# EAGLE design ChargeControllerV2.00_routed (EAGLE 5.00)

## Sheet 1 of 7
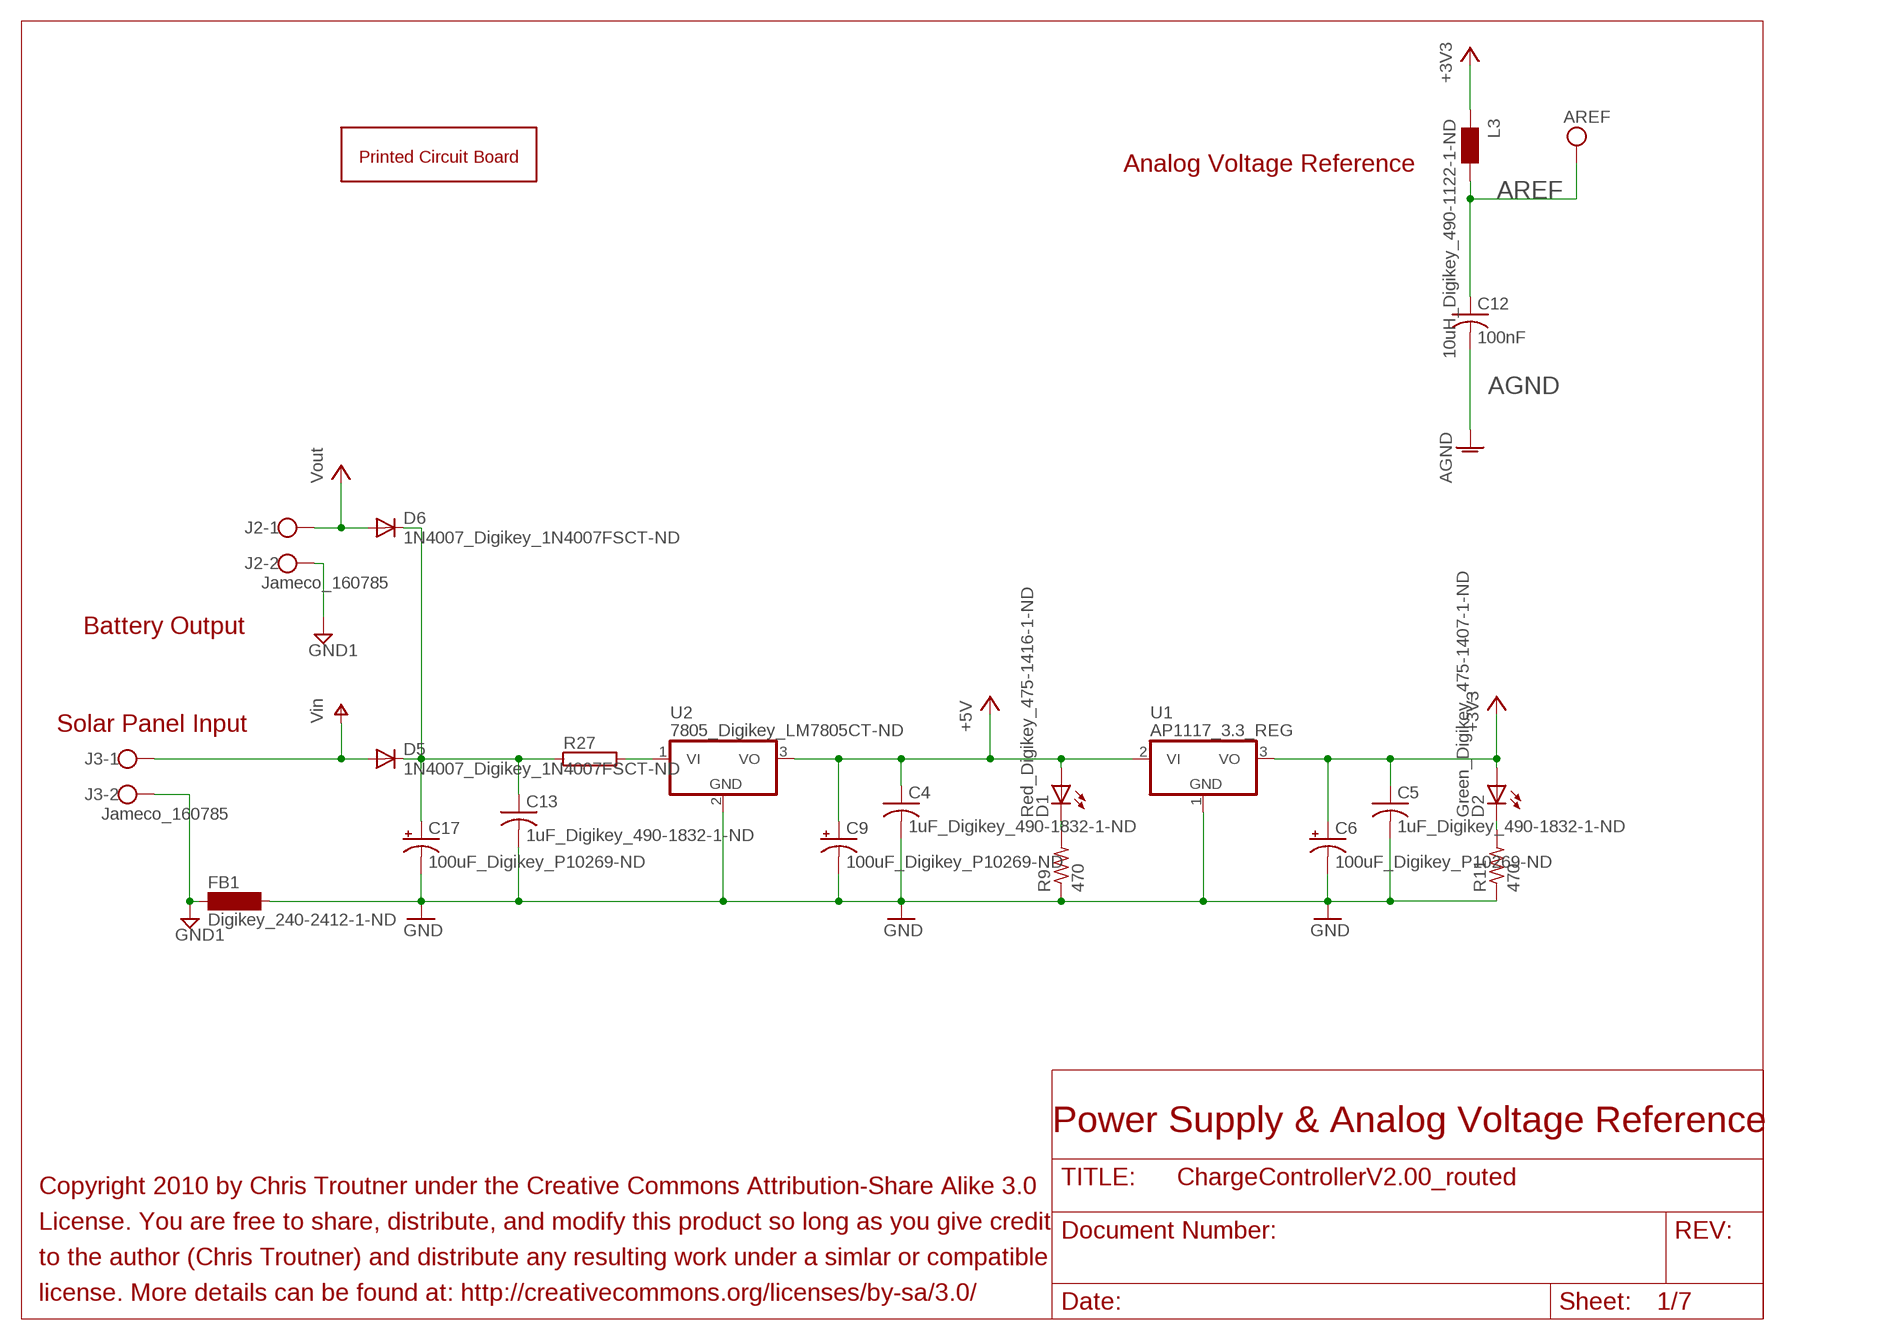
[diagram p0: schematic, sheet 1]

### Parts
C4  1uF_Digikey_490-1832-1-ND  C-USC1206K  [C1206K]
C5  1uF_Digikey_490-1832-1-ND  C-USC1206K  [C1206K]
C6  100uF_Digikey_P10269-ND  CPOL-USE2.5-7  [E2,5-7]
C9  100uF_Digikey_P10269-ND  CPOL-USE2.5-7  [E2,5-7]
C12  100nF  C-USC1206K  [C1206K]
C13  1uF_Digikey_490-1832-1-ND  C-USC1206K  [C1206K]
C17  100uF_Digikey_P10269-ND  CPOL-USE2.5-7  [E2,5-7]
D1  Red_Digikey_475-1416-1-ND  LEDCHIPLED_1206  [CHIPLED_1206]
D2  Green_Digikey_475-1407-1-ND  LEDCHIPLED_1206  [CHIPLED_1206]
D5  1N4007_Digikey_1N4007FSCT-ND  1N4004  [DO41-10]
D6  1N4007_Digikey_1N4007FSCT-ND  1N4004  [DO41-10]
FB1  Digikey_240-2412-1-ND  SM-1206  [SM-1206]
J2  Jameco_160785  W237-102  [W237-102]
J3  Jameco_160785  W237-102  [W237-102]
L3  10uH_Digikey_490-1122-1-ND  WE-MK_0805  [0805]
R9  470  R-US_R1206  [R1206]
R11  470  R-US_R1206  [R1206]
R27  RMPC70-2  [MPC70-2]
U1  AP1117_3.3_REG  [TO252]
U2  7805_Digikey_LM7805CT-ND  7805T  [TO220H]
U$1  PCB_RM2015S  [PCB_RM2015S]

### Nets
+3V3: C5.1 C6.+ D2.A L3.1 U1.3(VO) ; also sheet 6
+5V: C4.1 C9.+ D1.A U1.2(VI) U2.3(VO) ; also sheet 2,3,4,5,6
AGND: C12.2 ; also sheet 5
AREF: C12.1 L3.2
GND: C4.2 C5.2 C6.- C9.- C13.2 C17.- FB1.2 R9.1 R11.1 U1.1(GND) U2.2(GND) ; also sheet 2,3,4,5,6
GND1: FB1.1 J2.2 J3.2 ; also sheet 2
N$1: C13.1 C17.+ D5.C D6.C R27.1
N$3: R27.2 U2.1(VI)
N$5: D1.C R9.2
N$6: D2.C R11.2
N$35: D6.A J2.1 ; supply symbol labelled Vout ; also sheet 2,3
VIN: D5.A J3.1 ; supply symbol labelled Vin ; also sheet 2,3

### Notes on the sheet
- Analog Voltage Reference
- Battery Output
- Solar Panel Input
- Power Supply & Analog Voltage Reference
- Copyright 2010 by Chris Troutner under the Creative Commons Attribution-Share Alike 3.0
- License. You are free to share, distribute, and modify this product so long as you give credit
- to the author (Chris Troutner) and distribute any resulting work under a simlar or compatible
- license. More details can be found at: http://creativecommons.org/licenses/by-sa/3.0/

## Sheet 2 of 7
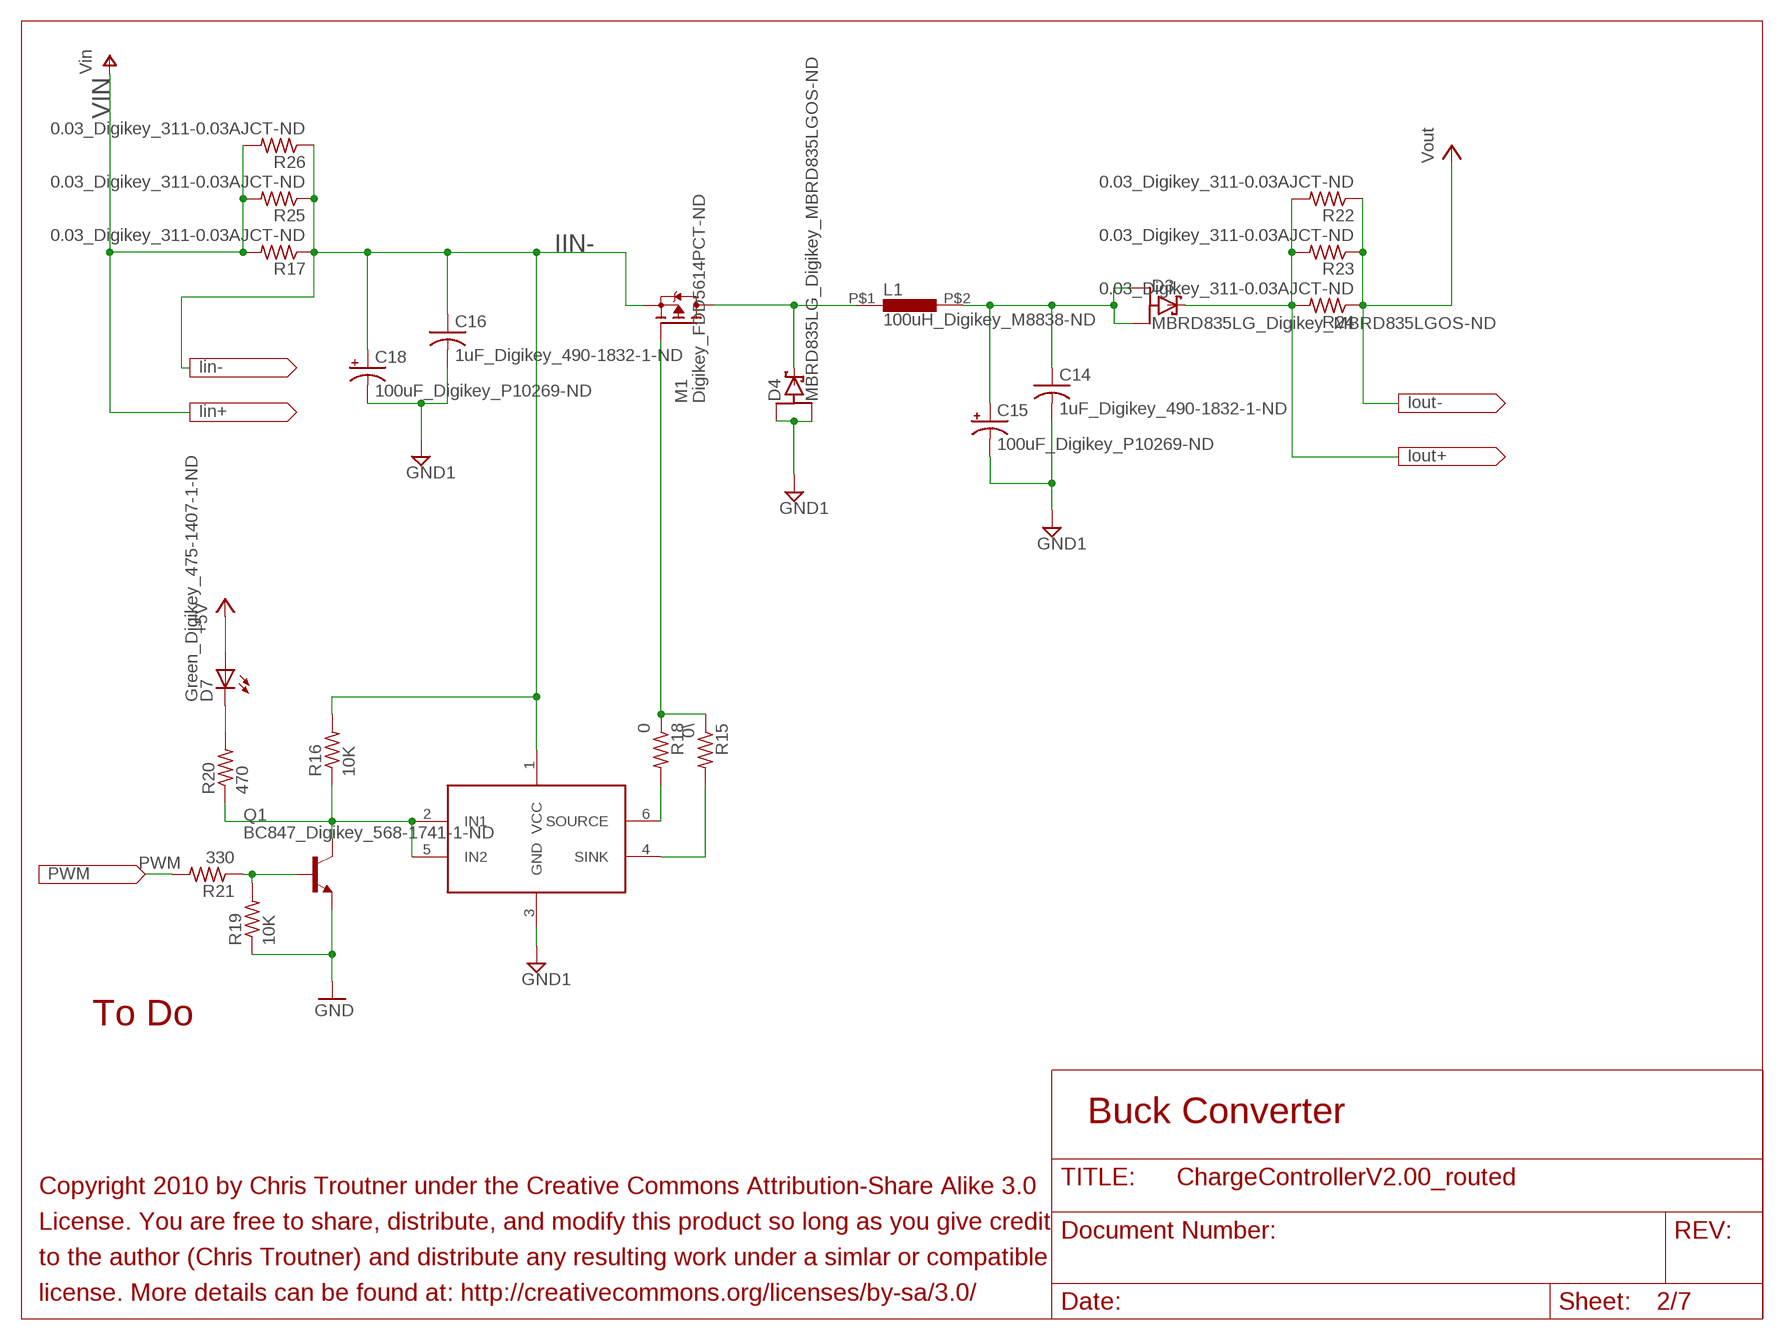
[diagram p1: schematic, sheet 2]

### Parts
C14  1uF_Digikey_490-1832-1-ND  C-USC1206K  [C1206K]
C15  100uF_Digikey_P10269-ND  CPOL-USE2.5-7  [E2,5-7]
C16  1uF_Digikey_490-1832-1-ND  C-USC1206K  [C1206K]
C18  100uF_Digikey_P10269-ND  CPOL-USE2.5-7  [E2,5-7]
D3  MBRD835LG_Digikey_MBRD835LGOS-ND  DIODE_SCHOTTKY_MBRD835LG  [DPAK_TO252]
D4  MBRD835LG_Digikey_MBRD835LGOS-ND  DIODE_SCHOTTKY_MBRD835LG  [DPAK_TO252]
D7  Green_Digikey_475-1407-1-ND  LEDCHIPLED_1206  [CHIPLED_1206]
L1  100uH_Digikey_M8838-ND  2312-RC  [2312-RC]
M1  Digikey_FDD5614PCT-ND  SPD30P06PTO252  [TO252]
Q1  BC847_Digikey_568-1741-1-ND  BC849SMD  [SOT23-BEC]
R15  0\  R-US_R1206  [R1206]
R16  10K  R-US_R1206  [R1206]
R17  0.03_Digikey_311-0.03AJCT-ND  R-US_R1206  [R1206]
R18  0  R-US_R1206  [R1206]
R19  10K  R-US_R1206  [R1206]
R20  470  R-US_R1206  [R1206]
R21  330  R-US_R1206  [R1206]
R22  0.03_Digikey_311-0.03AJCT-ND  R-US_R1206  [R1206]
R23  0.03_Digikey_311-0.03AJCT-ND  R-US_R1206  [R1206]
R24  0.03_Digikey_311-0.03AJCT-ND  R-US_R1206  [R1206]
R25  0.03_Digikey_311-0.03AJCT-ND  R-US_R1206  [R1206]
R26  0.03_Digikey_311-0.03AJCT-ND  R-US_R1206  [R1206]
U4  Digikey_ZXGD3003E6CT-ND  ZXGD3003  [SOT23-6]

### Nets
+5V: D7.A ; also sheet 1,3,4,5,6
GND: Q1.E R19.1 ; also sheet 1,3,4,5,6
GND1: C14.2 C15.- C16.2 C18.- D4.1(A) D4.3(A1) U4.3(GND) ; also sheet 1
IIN-: C16.1 C18.+ M1.2(S) R16.2 R17.1 R25.1 R26.1 U4.1(VCC) ; also sheet 3
IOUT+: D3.4(C) R22.2 R23.2 R24.2 ; also sheet 3
N$8: R18.2 U4.6(SOURCE)
N$9: D7.C R20.2
N$10: Q1.B R19.2 R21.1
N$16: R15.2 U4.4(SINK)
N$21: M1.1(G) R15.1 R18.1
N$24: Q1.C R16.1 R20.1 U4.2(IN1) U4.5(IN2)
N$30: D4.4(C) L1.P$1 M1.3(D)
N$34: C14.1 C15.+ D3.1(A) D3.3(A1) L1.P$2
N$35: R22.1 R23.1 R24.1 ; supply symbol labelled Vout ; also sheet 1,3
PWM: R21.2 ; also sheet 5
VIN: R17.2 R25.2 R26.2 ; supply symbol labelled Vin ; also sheet 1,3

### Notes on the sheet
- To Do
- Buck Converter
- Copyright 2010 by Chris Troutner under the Creative Commons Attribution-Share Alike 3.0
- License. You are free to share, distribute, and modify this product so long as you give credit
- to the author (Chris Troutner) and distribute any resulting work under a simlar or compatible
- license. More details can be found at: http://creativecommons.org/licenses/by-sa/3.0/

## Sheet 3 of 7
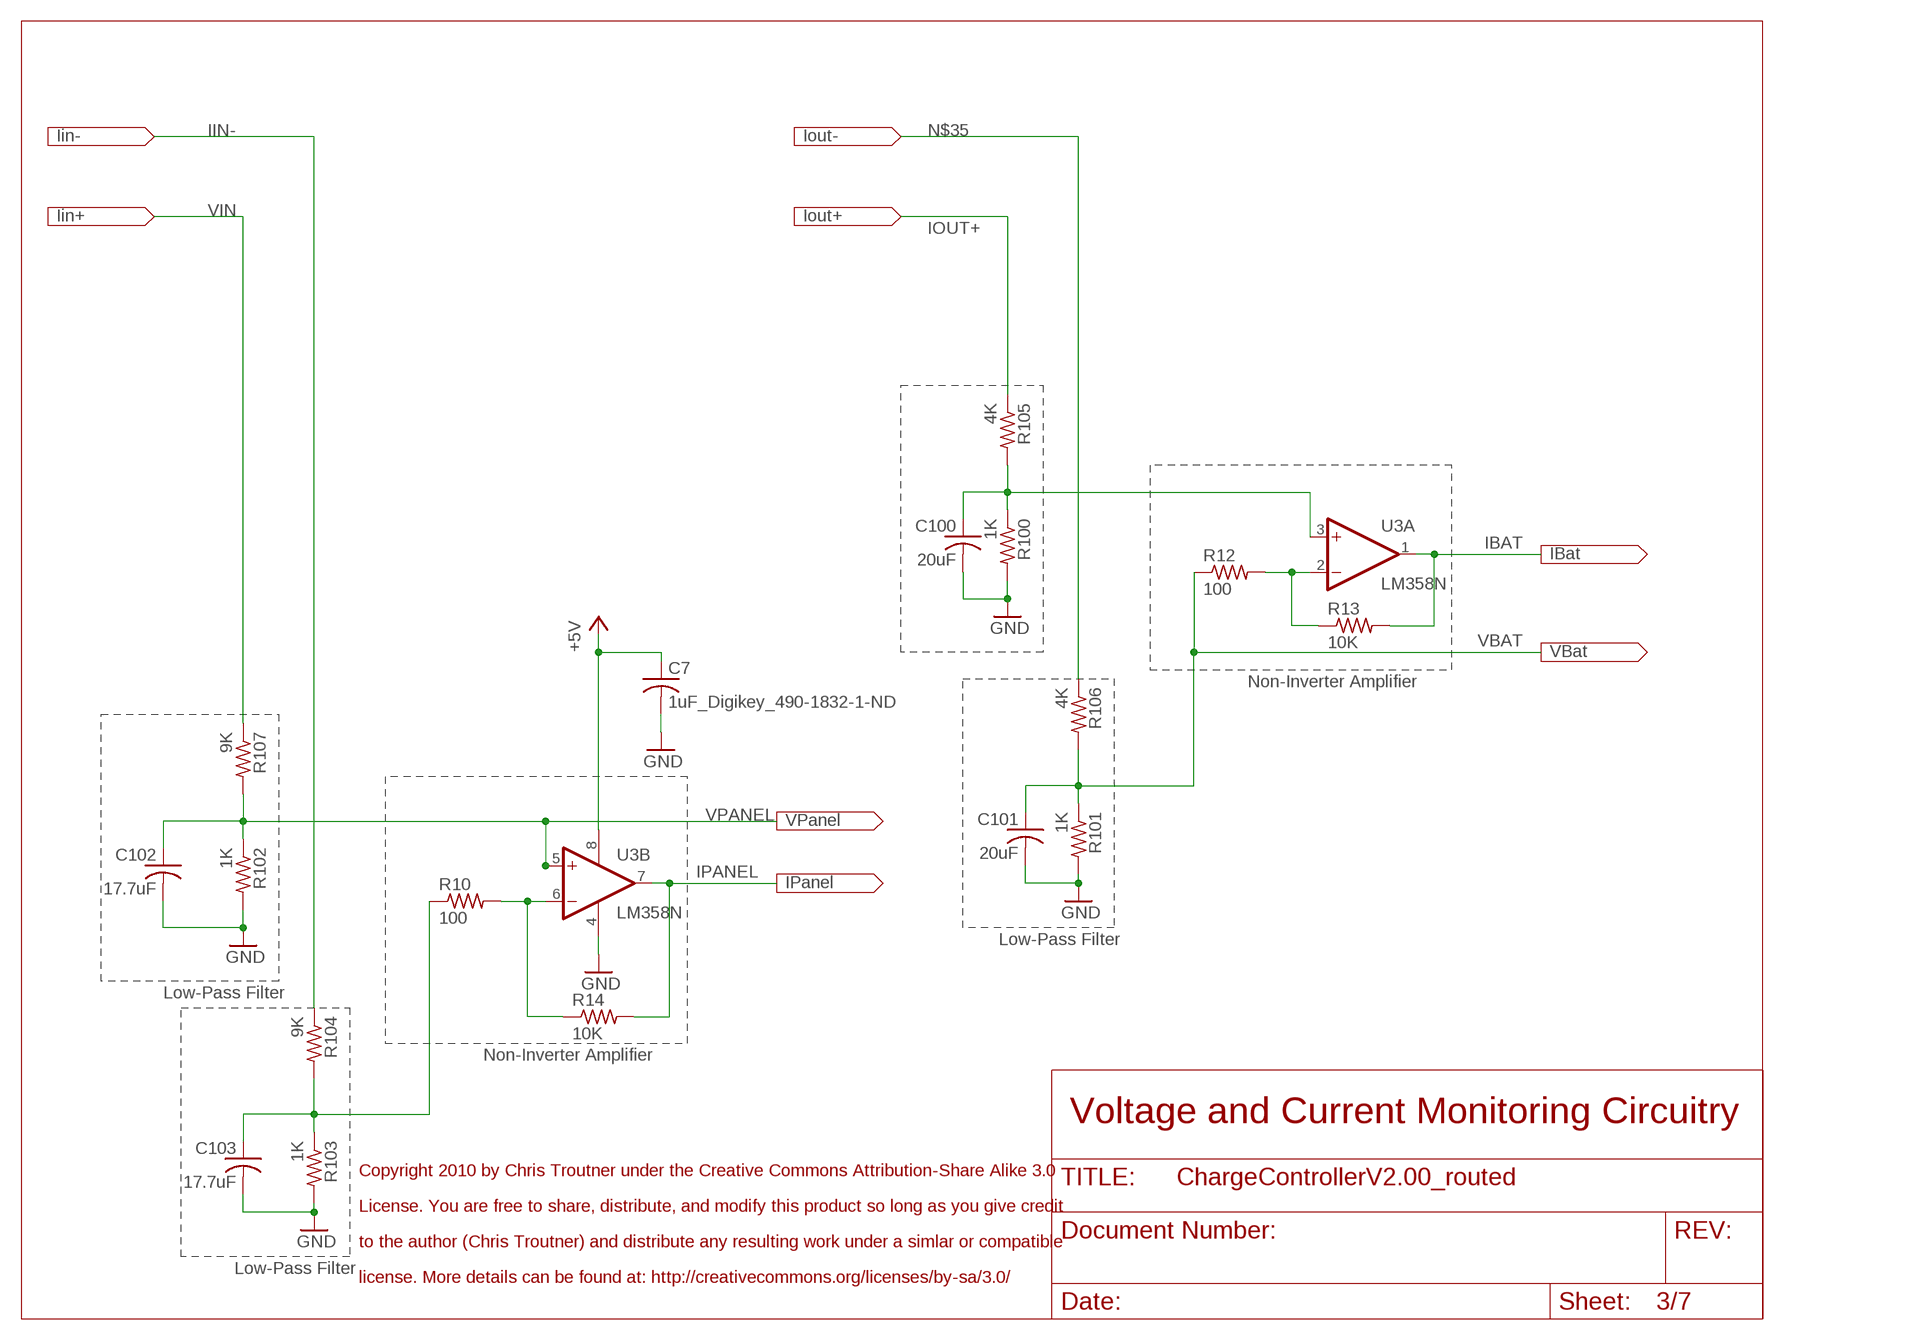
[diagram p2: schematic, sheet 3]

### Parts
C7  1uF_Digikey_490-1832-1-ND  C-USC1206K  [C1206K]
C100  20uF  C-USC1206K  [C1206K]
C101  20uF  C-USC1206K  [C1206K]
C102  17.7uF  C-USC1206K  [C1206K]
C103  17.7uF  C-USC1206K  [C1206K]
R10  100  R-US_R1206  [R1206]
R12  100  R-US_R1206  [R1206]
R13  10K  R-US_R1206  [R1206]
R14  10K  R-US_R1206  [R1206]
R100  1K  R-US_R1206  [R1206]
R101  1K  R-US_R1206  [R1206]
R102  1K  R-US_R1206  [R1206]
R103  1K  R-US_R1206  [R1206]
R104  9K  R-US_R1206  [R1206]
R105  4K  R-US_R1206  [R1206]
R106  4K  R-US_R1206  [R1206]
R107  9K  R-US_R1206  [R1206]
U3  LM358N  [DIL08]

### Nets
+5V: C7.1 U3.8(P:V+) ; also sheet 1,2,4,5,6
BLAH1: C103.1 R10.1 R103.1 R104.2
GND: C7.2 C100.2 C101.2 C102.2 C103.2 R100.2 R101.2 R102.2 R103.2 U3.4(P:V-) ; also sheet 1,2,4,5,6
IBAT: R13.2 U3.1(A:OUT) ; also sheet 5
IIN-: R104.1 ; also sheet 2
IOUT+: R105.1 ; also sheet 2
IPANEL: R14.2 U3.7(B:OUT) ; also sheet 5
N$12: R12.2 R13.1 U3.2(A:-IN)
N$14: R10.2 R14.1 U3.6(B:-IN)
N$35: R106.1 ; also sheet 1,2
VBAT: C101.1 R12.1 R101.1 R106.2 ; also sheet 5
VIN: R107.1 ; also sheet 1,2
VOP+: C100.1 R100.1 R105.2 U3.3(A:+IN)
VPANEL: C102.1 R102.1 R107.2 U3.5(B:+IN) ; also sheet 5

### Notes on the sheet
- Non-Inverter Amplifier
- Low-Pass Filter
- Low-Pass Filter
- Non-Inverter Amplifier
- Voltage and Current Monitoring Circuitry
- Copyright 2010 by Chris Troutner under the Creative Commons Attribution-Share Alike 3.0
- License. You are free to share, distribute, and modify this product so long as you give credit
- to the author (Chris Troutner) and distribute any resulting work under a simlar or compatible
- Low-Pass Filter
- license. More details can be found at: http://creativecommons.org/licenses/by-sa/3.0/

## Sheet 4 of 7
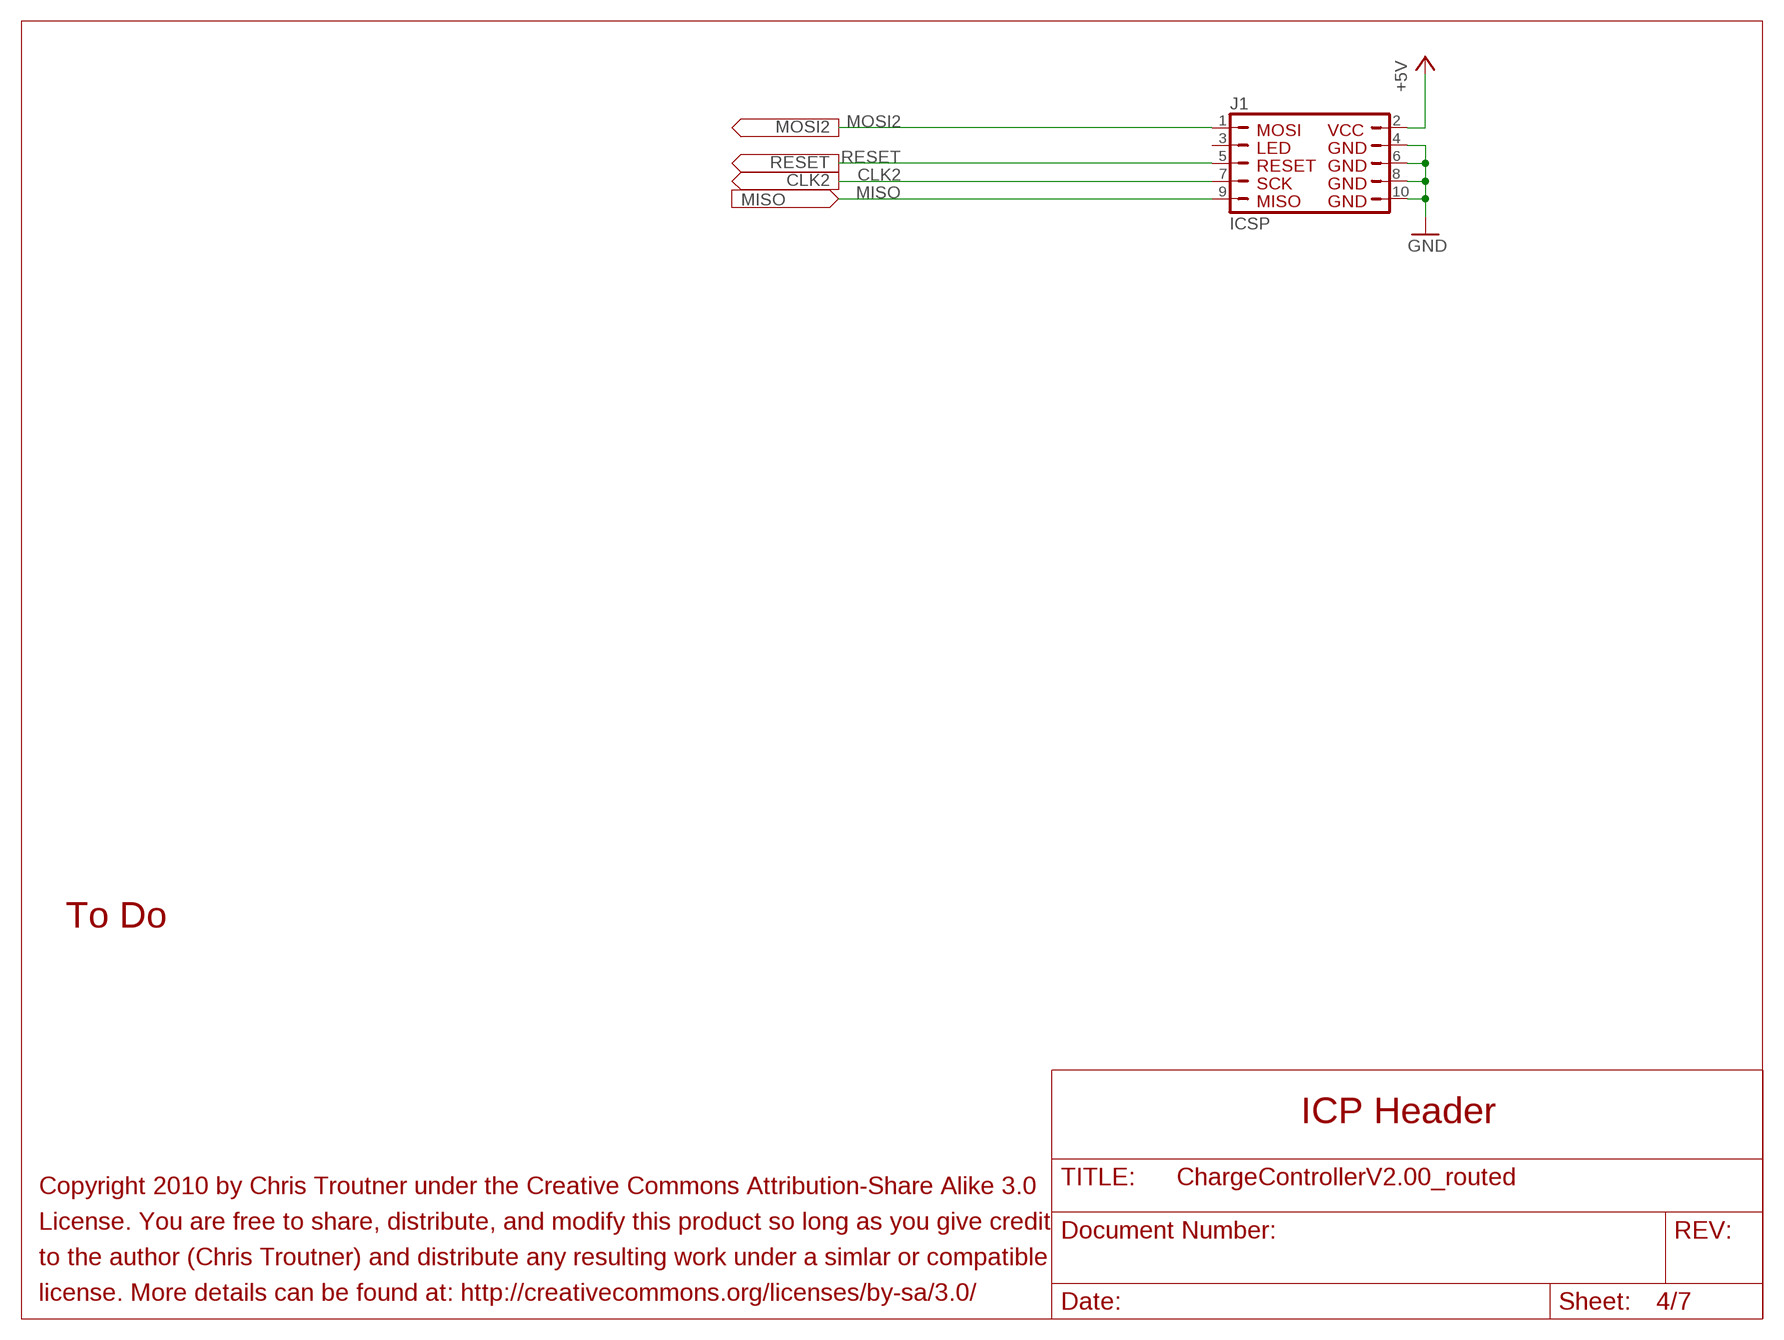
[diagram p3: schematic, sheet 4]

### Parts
J1  ICSP  [ICSP]

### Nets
+5V: J1.2 ; also sheet 1,2,3,5,6
CLK2: J1.7 ; also sheet 5,6
GND: J1.4 J1.6 J1.8 J1.10 ; also sheet 1,2,3,5,6
MISO: J1.9 ; also sheet 5,6
MOSI2: J1.1 ; also sheet 5,6
RESET: J1.5 ; also sheet 5
Unconnected: J1.3

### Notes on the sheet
- To Do
- ICP Header
- Copyright 2010 by Chris Troutner under the Creative Commons Attribution-Share Alike 3.0
- License. You are free to share, distribute, and modify this product so long as you give credit
- to the author (Chris Troutner) and distribute any resulting work under a simlar or compatible
- license. More details can be found at: http://creativecommons.org/licenses/by-sa/3.0/

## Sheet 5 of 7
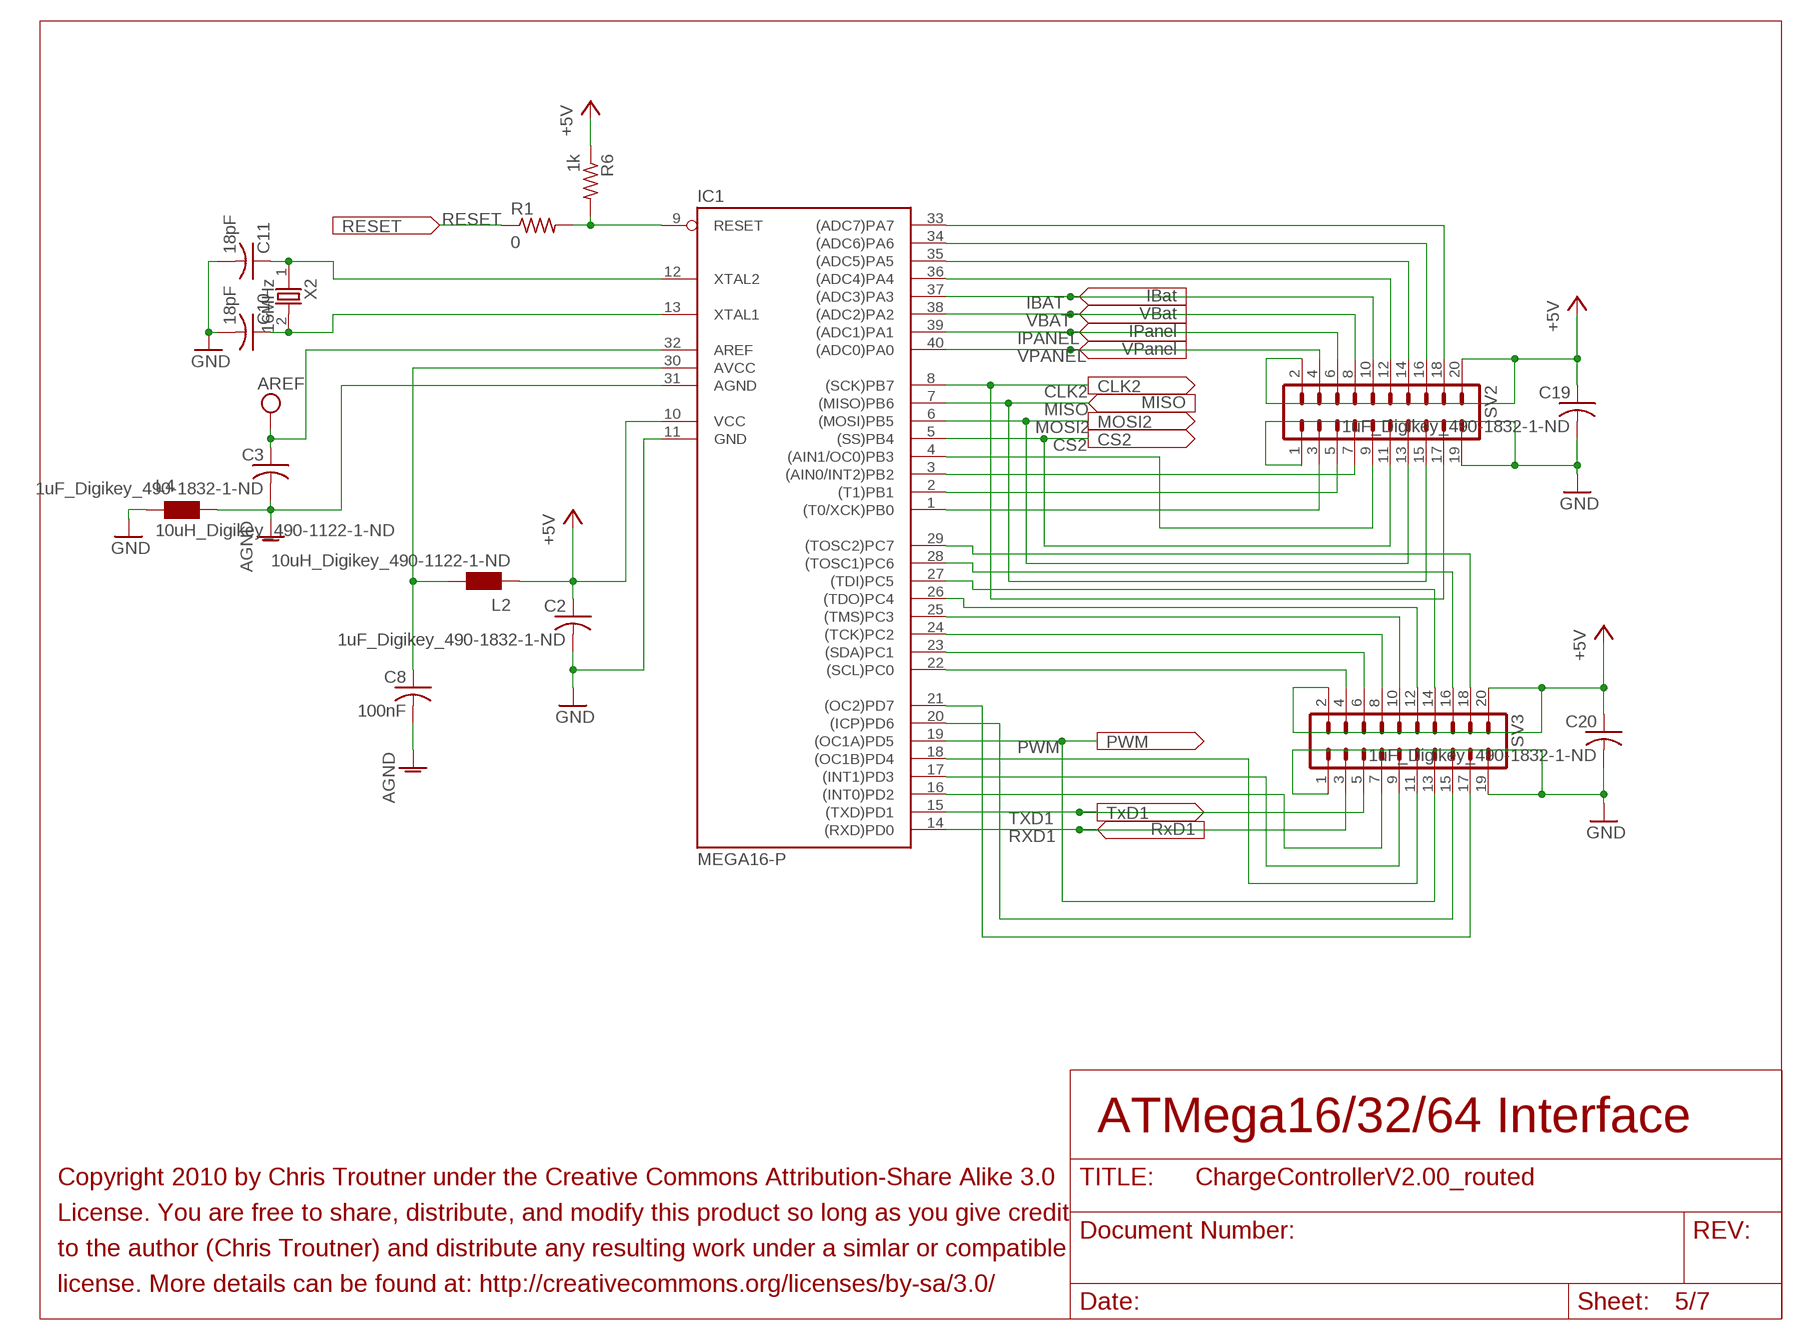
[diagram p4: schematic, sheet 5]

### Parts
C2  1uF_Digikey_490-1832-1-ND  C-USC1206K  [C1206K]
C3  1uF_Digikey_490-1832-1-ND  C-USC1206K  [C1206K]
C8  100nF  C-USC1206K  [C1206K]
C10  18pF  C-USC1206K  [C1206K]
C11  18pF  C-USC1206K  [C1206K]
C19  1uF_Digikey_490-1832-1-ND  C-USC1206K  [C1206K]
C20  1uF_Digikey_490-1832-1-ND  C-USC1206K  [C1206K]
IC1  MEGA16-P  [DIL40]
L2  10uH_Digikey_490-1122-1-ND  WE-MK_0805  [0805]
L4  10uH_Digikey_490-1122-1-ND  WE-MK_0805  [0805]
R1  0  R-US_R1206  [R1206]
R6  1k  R-US_R1206  [R1206]
SV2  MA10-2  [MA10-2]
SV3  MA10-2  [MA10-2]
X2  16MHz  20MHZ_XTL  [HS49S]

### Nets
+5V: C2.1 C19.1 C20.1 IC1.10(VCC) L2.1 R6.1 SV2.2 SV2.20 SV3.2 SV3.20 ; also sheet 1,2,3,4,6
AGND: C3.2 C8.2 IC1.31(AGND) L4.2 ; also sheet 1
CLK2: IC1.8((SCK)PB7) SV2.17 ; also sheet 4,6
CS2: IC1.5((SS)PB4) SV2.11 ; also sheet 6
GND: C2.2 C10.2 C11.2 C19.2 C20.2 IC1.11(GND) L4.1 SV2.1 SV2.19 SV3.1 SV3.19 ; also sheet 1,2,3,4,6
IBAT: IC1.37((ADC3)PA3) SV2.10 ; also sheet 3
IPANEL: IC1.39((ADC1)PA1) SV2.6 ; also sheet 3
MISO: IC1.7((MISO)PB6) SV2.15 ; also sheet 4,6
MOSI2: IC1.6((MOSI)PB5) SV2.13 ; also sheet 4,6
N$7: C8.1 IC1.30(AVCC) L2.2
N$15: C11.1 IC1.12(XTAL2) X2.1
N$17: C10.1 IC1.13(XTAL1) X2.2
N$18: IC1.9(RESET) R1.2 R6.2
N$19: IC1.33((ADC7)PA7) SV2.18
N$20: IC1.34((ADC6)PA6) SV2.16
N$22: IC1.35((ADC5)PA5) SV2.14
N$23: IC1.36((ADC4)PA4) SV2.12
N$27: IC1.1((T0/XCK)PB0) SV2.3
N$62: IC1.2((T1)PB1) SV2.5
N$67: IC1.3((AIN0/INT2)PB2) SV2.7
N$68: IC1.4((AIN1/OC0)PB3) SV2.9
N$69: IC1.16((INT0)PD2) SV3.7
N$70: IC1.17((INT1)PD3) SV3.9
N$71: IC1.22((SCL)PC0) SV3.4
N$72: IC1.23((SDA)PC1) SV3.6
N$73: IC1.24((TCK)PC2) SV3.8
N$74: IC1.25((TMS)PC3) SV3.10
N$75: IC1.26((TDO)PC4) SV3.12
N$76: IC1.27((TDI)PC5) SV3.14
N$77: IC1.28((TOSC1)PC6) SV3.16
N$78: IC1.29((TOSC2)PC7) SV3.18
N$79: IC1.18((OC1B)PD4) SV3.11
N$80: IC1.20((ICP)PD6) SV3.15
N$81: IC1.21((OC2)PD7) SV3.17
PWM: IC1.19((OC1A)PD5) SV3.13 ; also sheet 2
RESET: R1.1 ; also sheet 4
RXD1: IC1.14((RXD)PD0) SV3.3 ; also sheet 6
TXD1: IC1.15((TXD)PD1) SV3.5 ; also sheet 6
VBAT: IC1.38((ADC2)PA2) SV2.8 ; also sheet 3
VDD: C3.1 IC1.32(AREF) ; supply symbol labelled AREF
VPANEL: IC1.40((ADC0)PA0) SV2.4 ; also sheet 3

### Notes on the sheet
- ATMega16/32/64 Interface
- Copyright 2010 by Chris Troutner under the Creative Commons Attribution-Share Alike 3.0
- License. You are free to share, distribute, and modify this product so long as you give credit
- to the author (Chris Troutner) and distribute any resulting work under a simlar or compatible
- license. More details can be found at: http://creativecommons.org/licenses/by-sa/3.0/

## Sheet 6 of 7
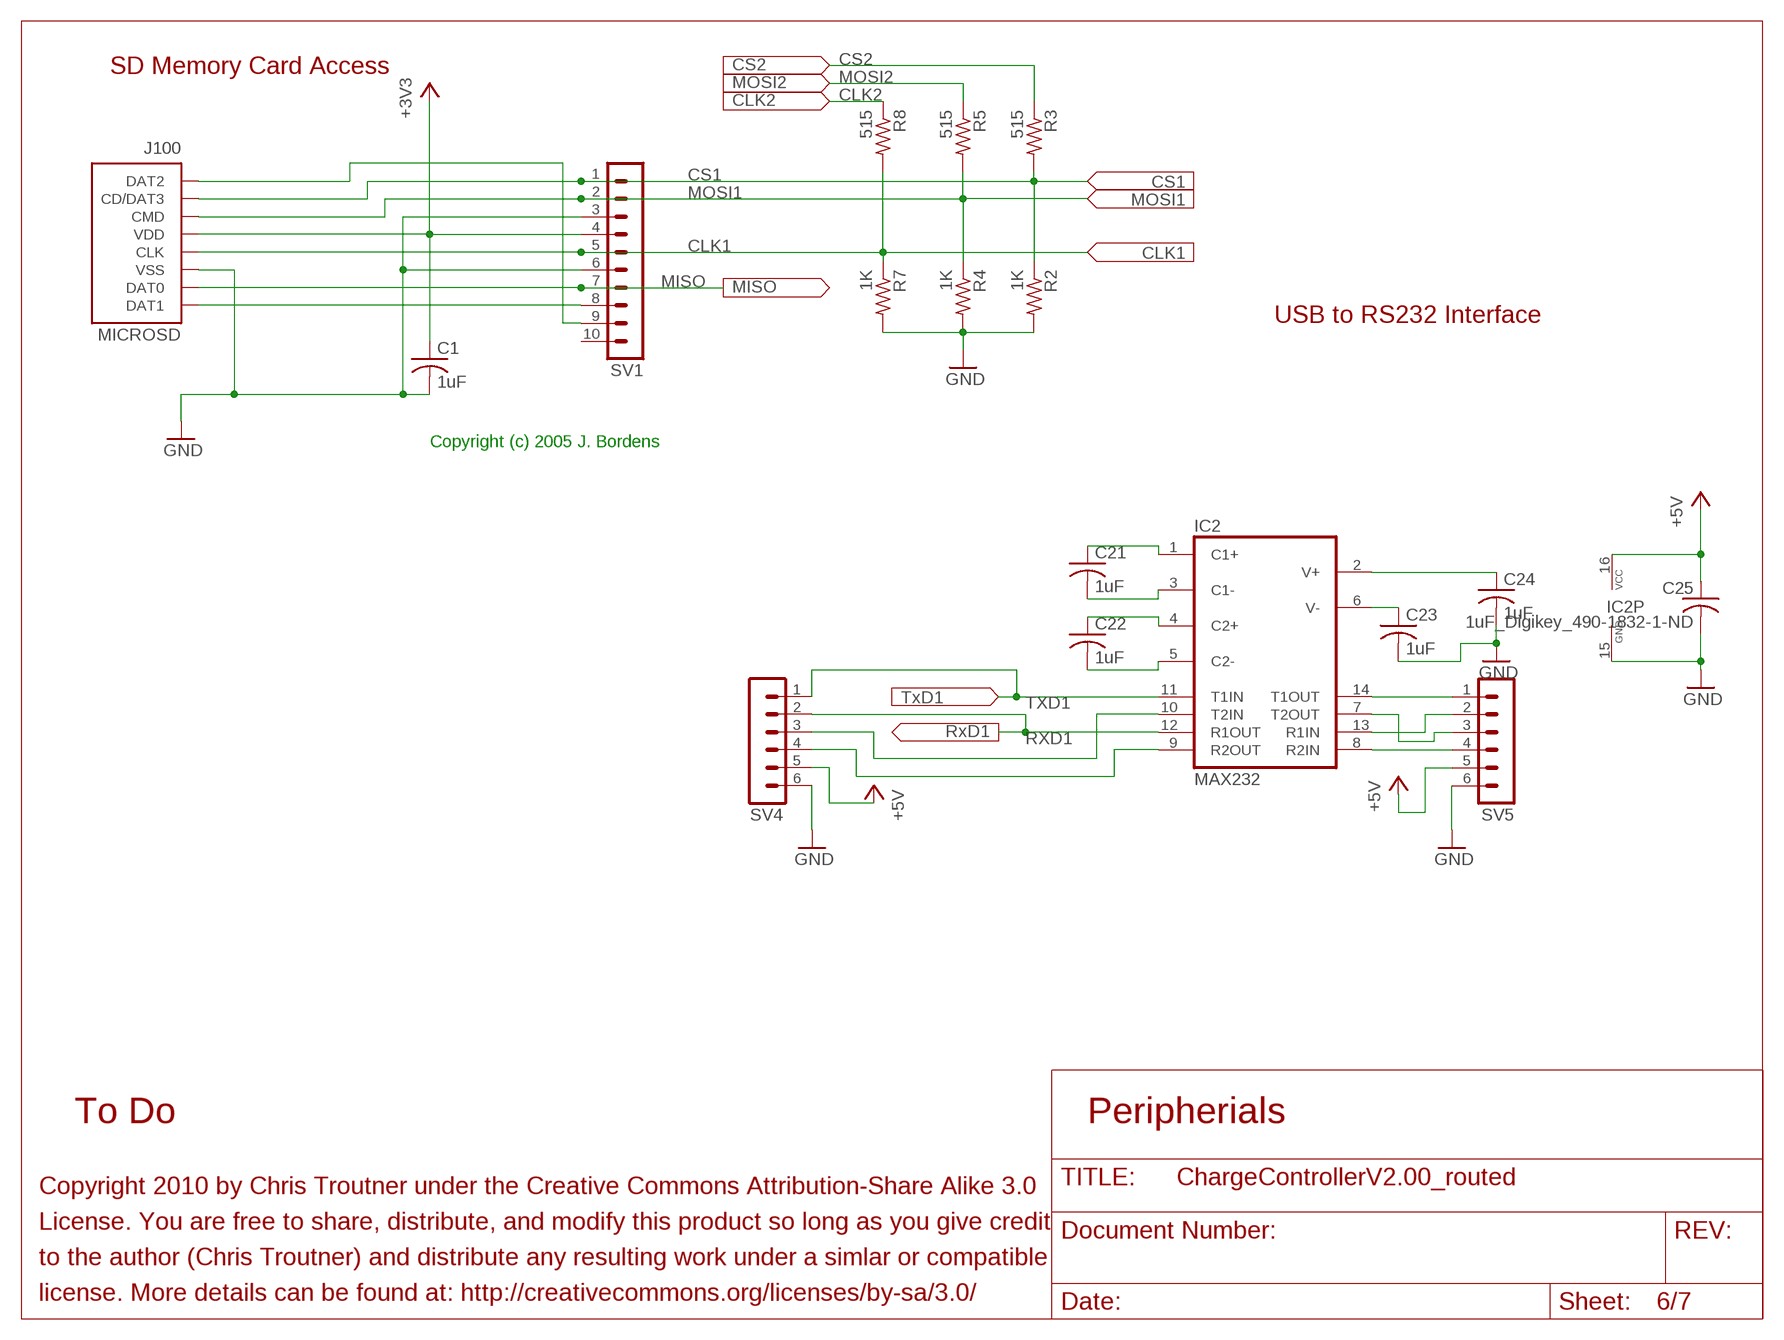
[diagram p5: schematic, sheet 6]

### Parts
C1  1uF  C-USC1206K  [C1206K]
C21  1uF  C-USC1206K  [C1206K]
C22  1uF  C-USC1206K  [C1206K]
C23  1uF  C-USC1206K  [C1206K]
C24  1uF  C-USC1206K  [C1206K]
C25  1uF_Digikey_490-1832-1-ND  C-USC1206K  [C1206K]
IC2  MAX232  [DIL16]
J100  MICROSD  [DM3D_SD_MEMORY]
R2  1K  R-US_R1206  [R1206]
R3  515  R-US_R1206  [R1206]
R4  1K  R-US_R1206  [R1206]
R5  515  R-US_R1206  [R1206]
R7  1K  R-US_R1206  [R1206]
R8  515  R-US_R1206  [R1206]
SV1  MA10-1  [MA10-1]
SV4  MA06-1  [MA06-1]
SV5  MA06-1  [MA06-1]

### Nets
+3V3: C1.1 J100.P$5(VDD) SV1.4 ; also sheet 1
+5V: C25.1 IC2.16(VCC) SV4.5 SV5.5 ; also sheet 1,2,3,4,5
CLK1: J100.P$4(CLK) R7.1 R8.2 SV1.5
CLK2: R8.1 ; also sheet 4,5
CS1: J100.P$7(CD/DAT3) R2.1 R3.2 SV1.1
CS2: R3.1 ; also sheet 5
GND: C1.2 C23.2 C24.2 C25.2 IC2.15(GND) J100.P$3(VSS) R2.2 R4.2 R7.2 SV1.3 SV1.6 SV4.6 SV5.6 ; also sheet 1,2,3,4,5
MISO: J100.P$2(DAT0) SV1.7 ; also sheet 4,5
MOSI1: J100.P$6(CMD) R4.1 R5.2 SV1.2
MOSI2: R5.1 ; also sheet 4,5
N$2: C22.1 IC2.4(C2+)
N$4: C22.2 IC2.5(C2-)
N$11: C21.2 IC2.3(C1-)
N$13: C21.1 IC2.1(C1+)
N$26: J100.P$8(DAT2) SV1.9
N$28: C23.1 IC2.6(V-)
N$29: J100.P$1(DAT1) SV1.8
N$31: C24.1 IC2.2(V+)
N$32: IC2.10(T2IN) SV4.3
N$33: IC2.9(R2OUT) SV4.4
N$36: IC2.14(T1OUT) SV5.1
N$37: IC2.13(R1IN) SV5.2
N$38: IC2.7(T2OUT) SV5.3
N$39: IC2.8(R2IN) SV5.4
RXD1: IC2.12(R1OUT) SV4.2 ; also sheet 5
TXD1: IC2.11(T1IN) SV4.1 ; also sheet 5
Unconnected: SV1.10

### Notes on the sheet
- SD Memory Card Access
- USB to RS232 Interface
- Copyright (c) 2005 J. Bordens
- To Do | Peripherials
- Copyright 2010 by Chris Troutner under the Creative Commons Attribution-Share Alike 3.0
- License. You are free to share, distribute, and modify this product so long as you give credit
- to the author (Chris Troutner) and distribute any resulting work under a simlar or compatible
- license. More details can be found at: http://creativecommons.org/licenses/by-sa/3.0/

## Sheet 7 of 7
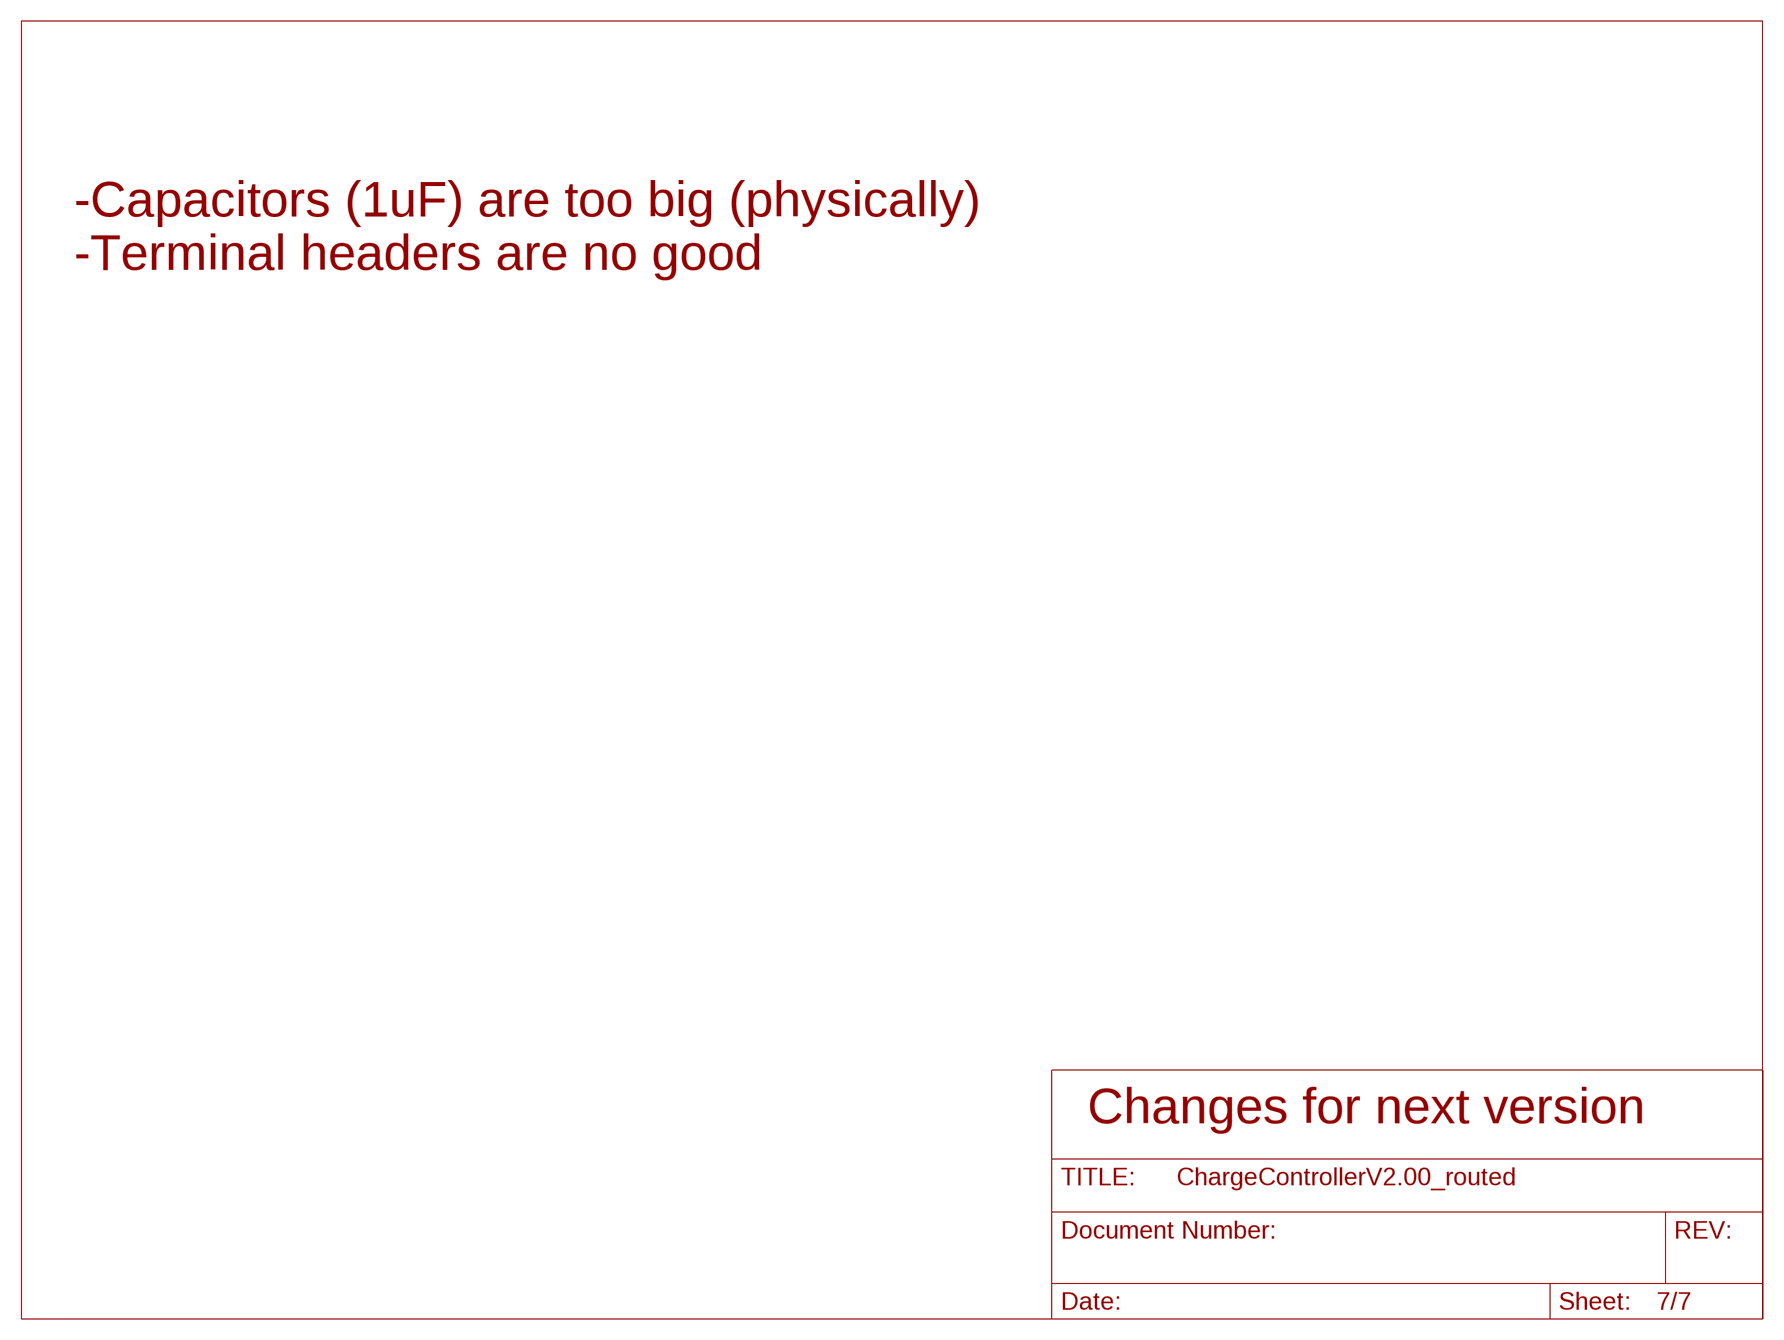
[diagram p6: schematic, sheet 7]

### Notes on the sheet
- -Capacitors (1uF) are too big (physically)
- -Terminal headers are no good
- Changes for next version

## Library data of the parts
C1-C5 C7 C8 C10-C14 C16 C19-C25 C100-C103 = rcl:C-US: CAPACITOR, American symbol
C6 C9 C15 C17 C18 = rcl:CPOL-US: POLARIZED CAPACITOR, American symbol
D1 D2 D7 = led:LED: LED
D3 D4 = EV:DIODE_SCHOTTKY_MBRD835LG: Schottkey diode from ON Semiconductor part # MBRD835LG. Digikey # MBRD835LGOS-ND
D5 D6 = diode:1N4004: DIODE
FB1 = inductor-neosid:SM-1206: INDUCTOR
IC1 = atmel:MEGA16-P: MICROCONTROLLER 16 Kbytes FLASH 1 kbytes SRAM 512 bytes EEPROM USART 8-channel 10 bit ADC Source: avr.lbr
IC2 = maxim:MAX232: RS232 TRANSEIVER
J1 = EV:ICSP: ICSP header for programming AVR microcontrollers
J2 J3 = con-wago-500:W237-102: WAGO SCREW CLAMP
J100 = ChargeController:MICROSD: MicroSD Card Interface. DM3D-SF from Hirose. Digikey # HR1941CT-ND
L1 = EV:2312-RC: Bourns 2312-H-RC. Digikey # M8838-ND. 100uH 7amps toroid
L2-L4 = wuerth-elektronik:WE-MK: SMD Multilayer Ceramic Inductors WE-MK
M1 = transistor-fet:SPD30P06P: SIPMOS(R) Power-Transistor P-Channel, Enhancement mode Source: http://www.infineon.com/upload/Document/cmc_upload/documents/012/3615/SPD_U30P06P.pdf
Q1 = transistor-npn:BC849*: NPN Transistor
R1-R26 R100-R107 = resistor:R-US_: RESISTOR, American symbol
R27 = resistor-power:R: Power Resitor
SV1 = con-lstb:MA10-1: PIN HEADER
SV2 SV3 = con-lstb:MA10-2: PIN HEADER
SV4 SV5 = con-lstb:MA06-1: PIN HEADER
U1 = ChargeController:AP1117_3.3_REG: AP1117 3.3V Regulator. Digikey # AP1117D33GCT-ND
U2 = linear:78*: Positive VOLTAGE REGULATOR Source: http://cache.national.com/ds/LM/LM78L05.pdf http://www.fairchildsemi.com/ds/LM/LM7805.pdf
U3 = linear:LM358: OP AMP also LM158; LM258; LM2904 Source: http://cache.national.com/ds/LM/LM158.pdf
U4 = EV:ZXGD3003
U$1 = EV:PCB_RM2015S: Hammond Manufacturing RM2015S Project Box
X2 = EV:20MHZ_XTL

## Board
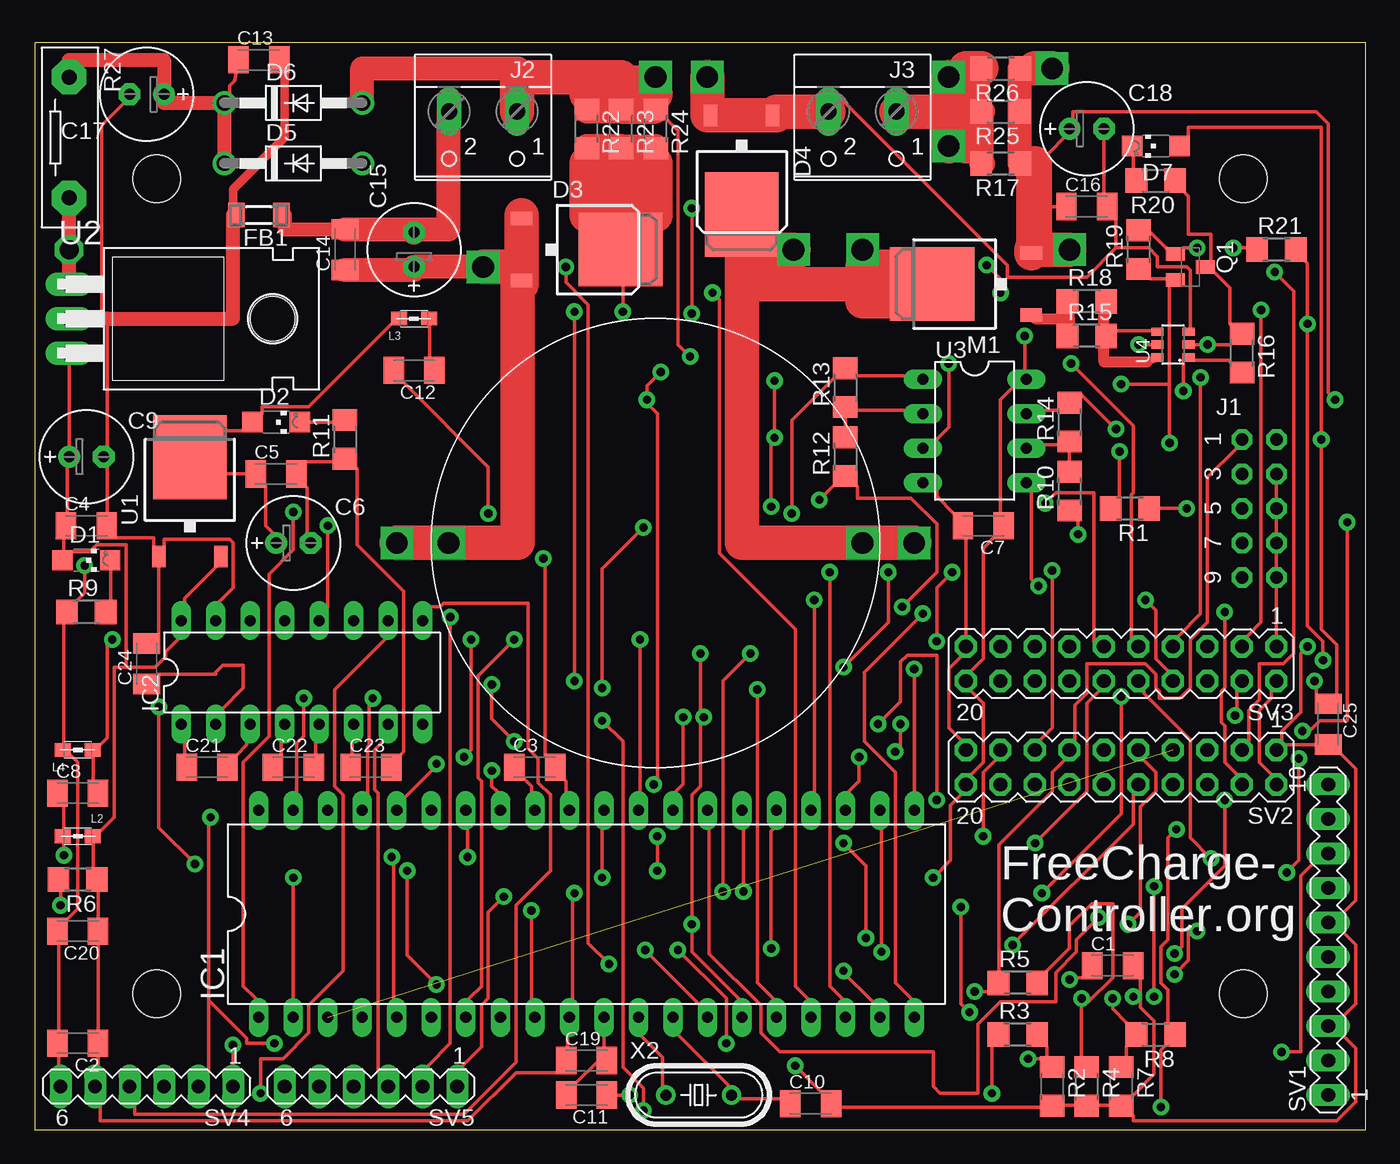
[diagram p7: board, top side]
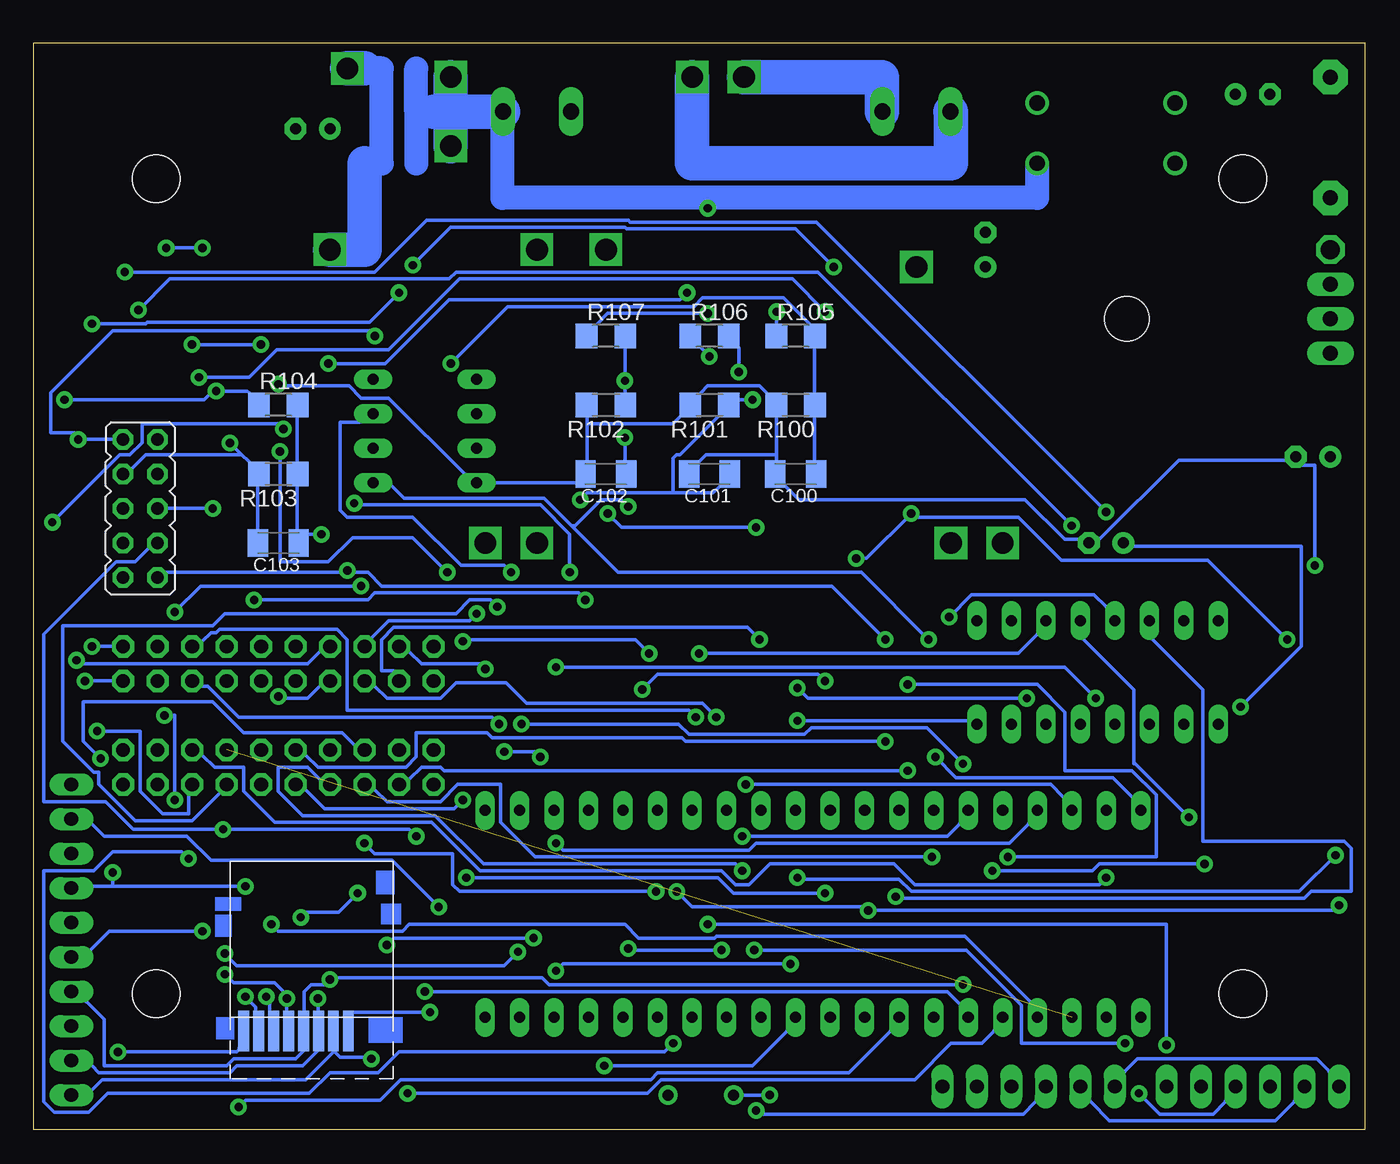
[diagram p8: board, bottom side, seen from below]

Size 98 x 80 mm. Coordinates in mm from the lower left corner, seen from the top.
Copper layers (1*16): Top 0.035mm / dielectric 1.5mm / Bottom 0.035mm
Design rules "default *": minimum track width 10mil, minimum drill 24mil, track to track 10mil, track to pad 10mil, pad to pad 10mil, via to via 10mil, smd to smd 0mil, copper to edge 20mil, drill to drill 24mil, minimum pad ring 12mil, minimum via ring 12mil, stop-mask expansion 4mil, vias tented up to drill 0mil, thermal gap 10mil
tKeepout: area 5.1,66 to 12.7,73.7; area 85.1,66 to 92.7,73.7; area 85.1,6.3 to 92.7,14; area 5.1,6.3 to 12.7,14
bKeepout: area 5.1,6.3 to 12.7,14; area 85.1,6.3 to 92.7,14; area 85.1,66 to 92.7,73.7; area 5.1,66 to 12.7,73.7
tRestrict: area 5.1,6.3 to 12.7,14; area 85.1,6.3 to 92.7,14; area 85.1,66 to 92.7,73.7; area 5.1,66 to 12.7,73.7
bRestrict: area 5.1,6.3 to 12.7,14; area 85.1,6.3 to 92.7,14; area 85.1,66 to 92.7,73.7; area 5.1,66 to 12.7,73.7

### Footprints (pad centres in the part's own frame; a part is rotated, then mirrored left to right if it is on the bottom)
C1206K = smd 1.5 x 2: 1 -1.5,0; 2 1.5,0
E2,5-7 = drill 0.813 pad 1.6 round: + -1.27,0 | drill 0.813 pad 1.6 octagon: - 1.27,0
CHIPLED_1206 = smd 1.5 x 1.5: A 0,-1.75; C 0,1.75
DPAK_TO252 = smd 1 x 1.6: 1 -2.28,-6.07; 3 2.28,-6.07 | smd 5.4 x 6.2: 4 0,1.23
DO41-10 = drill 1.118 round: A 5.08,0; C -5.08,0
SM-1206 = smd 1.2 x 1.8: 1 -1.65,0; 2 1.65,0
DIL40 = drill 0.813 long: 1 -24.13,-7.62; 2 -21.59,-7.62; 3 -19.05,-7.62; 4 -16.51,-7.62; 5 -13.97,-7.62; 6 -11.43,-7.62; 7 -8.89,-7.62; 8 -6.35,-7.62; 9 -3.81,-7.62; 10 -1.27,-7.62; 11 1.27,-7.62; 12 3.81,-7.62; 13 6.35,-7.62; 14 8.89,-7.62; 15 11.43,-7.62; 16 13.97,-7.62; 17 16.51,-7.62; 18 19.05,-7.62; 19 21.59,-7.62; 20 24.13,-7.62; 21 24.13,7.62; 22 21.59,7.62; 23 19.05,7.62; 24 16.51,7.62; 25 13.97,7.62; 26 11.43,7.62; 27 8.89,7.62; 28 6.35,7.62; 29 3.81,7.62; 30 1.27,7.62; 31 -1.27,7.62; 32 -3.81,7.62; 33 -6.35,7.62; 34 -8.89,7.62; 35 -11.43,7.62; 36 -13.97,7.62; 37 -16.51,7.62; 38 -19.05,7.62; 39 -21.59,7.62; 40 -24.13,7.62
DIL16 = drill 0.813 long: 1 -8.89,-3.81; 2 -6.35,-3.81; 3 -3.81,-3.81; 4 -1.27,-3.81; 5 1.27,-3.81; 6 3.81,-3.81; 7 6.35,-3.81; 8 8.89,-3.81; 9 8.89,3.81; 10 6.35,3.81; 11 3.81,3.81; 12 1.27,3.81; 13 -1.27,3.81; 14 -3.81,3.81; 15 -6.35,3.81; 16 -8.89,3.81
ICSP = drill 0.914 octagon: 1 -1.27,5.08; 2 1.27,5.08; 3 -1.27,2.54; 4 1.27,2.54; 5 -1.27,0; 6 1.27,0; 7 -1.27,-2.54; 8 1.27,-2.54; 9 -1.27,-5.08; 10 1.27,-5.08
W237-102 = drill 1.194 long: 1 -2.5,-1.27; 2 2.5,-1.27
DM3D_SD_MEMORY = smd 0.8 x 3: P$1 0,-1; P$2 1.1,-1; P$3 2.2,-1; P$4 3.3,-1; P$5 4.4,-1; P$6 5.5,-1; P$7 6.6,-1; P$8 7.7,-1
2312-RC = drill 1.6 square: P$1 0,-15.24; P$2 0,15.24
0805 = smd 1.2 x 1: 1 -1.1,0; 2 1.1,0
TO252 = smd 1 x 1.6: 1 -2.28,-4.8; 2 2.28,-4.8 | smd 5.4 x 6.2: 3 0,2.5
SOT23-BEC = smd 1 x 1.4: B -0.95,-1.1; C 0,1.1; E 0.95,-1.1
R1206 = smd 1.6 x 1.803: 1 -1.422,0; 2 1.422,0
MPC70-2 = drill 1.118 pad 2.54 octagon: 1 -4.445,0; 2 4.445,0
MA10-1 = drill 1.016 long: 1 -11.43,0; 2 -8.89,0; 3 -6.35,0; 4 -3.81,0; 5 -1.27,0; 6 1.27,0; 7 3.81,0; 8 6.35,0; 9 8.89,0; 10 11.43,0
MA10-2 = drill 1.016 octagon: 1 -11.43,-1.27; 2 -11.43,1.27; 3 -8.89,-1.27; 4 -8.89,1.27; 5 -6.35,-1.27; 6 -6.35,1.27; 7 -3.81,-1.27; 8 -3.81,1.27; 9 -1.27,-1.27; 10 -1.27,1.27; 11 1.27,-1.27; 12 1.27,1.27; 13 3.81,-1.27; 14 3.81,1.27; 15 6.35,-1.27; 16 6.35,1.27; 17 8.89,-1.27; 18 8.89,1.27; 19 11.43,-1.27; 20 11.43,1.27
MA06-1 = drill 1.016 long: 1 -6.35,0; 2 -3.81,0; 3 -1.27,0; 4 1.27,0; 5 3.81,0; 6 6.35,0
TO220H = drill 1.118 long: 1 -2.54,-10.16; 2 0,-10.16; 3 2.54,-10.16 | hole 3.302: 0,4.826
DIL08 = drill 0.813 long: 1 -3.81,-3.81; 2 -1.27,-3.81; 3 1.27,-3.81; 4 3.81,-3.81; 5 3.81,3.81; 6 1.27,3.81; 7 -1.27,3.81; 8 -3.81,3.81
SOT23-6 = smd 0.6 x 0.9: 1 -0.95,-1.15; 2 0,-1.15; 3 0.95,-1.15; 4 0.95,1.15; 5 0,1.15; 6 -0.95,1.15
PCB_RM2015S = hole 3.5: 9,70; 9,10; 89,10; 89,70
HS49S = drill 0.813 round: 1 -2.413,0; 2 2.413,0

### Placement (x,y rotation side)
C1  79.38,12.06 0 top
C2  3.17,6.35 180 top
C3  36.83,26.67 0 top
C4  3.81,44.45 0 top
C5  17.78,48.26 0 top
C6  19.05,43.18 0 top
C7  69.85,44.45 180 top
C8  3.17,24.77 0 top
C9  3.81,49.53 0 top
C10  57.15,1.91 0 top
C11  40.64,2.54 180 top
C12  27.94,55.88 180 top
C13  16.51,78.74 0 top
C14  22.86,64.77 90 top
C15  27.94,64.77 90 top
C16  77.47,67.94 0 top
C17  8.26,76.2 180 top
C18  77.47,73.66 0 top
C19  40.64,5.08 0 top
C20  3.17,14.61 180 top
C21  12.7,26.67 0 top
C22  19.05,26.67 0 top
C23  24.77,26.67 0 top
C24  8.26,34.29 90 top
C25  95.25,29.84 270 top
C100  41.91,48.26 180 bottom
C101  48.26,48.26 180 bottom
C102  55.88,48.26 180 bottom
C103  80.01,43.18 180 bottom
D1  3.81,41.91 270 top
D2  17.78,52.07 270 top
D3  41.91,64.77 270 top
D4  52.07,68.58 180 top
D5  19.05,71.12 0 top
D6  19.05,75.56 0 top
D7  82.55,72.39 90 top
FB1  16.51,67.31 180 top
IC1  40.64,15.88 0 top
IC2  19.68,33.66 0 top
J1  90.17,45.72 0 top
J2  33.02,73.66 180 top
J3  60.96,73.66 180 top
J100  82.55,8.26 0 bottom
L1  45.72,43.18 90 top
L2  3.17,21.59 180 top
L3  27.94,59.69 0 top
L4  3.17,27.94 0 top
M1  68.58,62.23 90 top
Q1  85.09,63.5 270 top
R1  80.64,45.72 180 top
R2  74.93,3.17 270 top
R3  72.39,6.99 0 top
R4  77.47,3.17 270 top
R5  72.39,10.79 0 top
R6  3.17,18.41 180 top
R7  80.01,3.17 270 top
R8  82.55,6.99 180 top
R9  3.81,38.1 0 top
R10  76.2,46.99 90 top
R11  22.86,50.8 90 top
R12  59.69,49.53 90 top
R13  59.69,54.61 90 top
R14  76.2,52.07 90 top
R15  77.47,58.42 0 top
R16  88.9,57.15 270 top
R17  71.12,71.12 180 top
R18  77.47,60.96 0 top
R19  81.28,64.77 90 top
R20  82.55,69.85 180 top
R21  91.44,64.77 0 top
R22  40.64,73.66 270 top
R23  43.18,73.66 270 top
R24  45.72,73.66 270 top
R25  71.12,74.93 180 top
R26  71.12,78.11 180 top
R27  2.54,73.03 270 top
R100  41.91,53.34 180 bottom
R101  48.26,53.34 180 bottom
R102  55.88,53.34 180 bottom
R103  80.01,48.26 180 bottom
R104  80.01,53.34 0 bottom
R105  41.91,58.42 0 bottom
R106  48.26,58.42 0 bottom
R107  55.88,58.42 0 bottom
SV1  95.25,13.97 90 top
SV2  80.01,26.67 180 top
SV3  80.01,34.29 180 top
SV4  8.26,3.17 180 top
SV5  24.77,3.17 180 top
U1  11.43,46.99 0 top
U2  12.7,59.69 270 top
U3  69.22,51.44 270 top
U4  83.82,57.78 90 top
U$1  0,0 0 top
X2  48.9,2.54 0 top

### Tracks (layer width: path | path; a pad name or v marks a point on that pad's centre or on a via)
+3V3  (via drill 0.61)
  Top 0.203: C5.1 16.51,48.26 | D2.A 16.51,52.07 | U1.3 11.94,46.48
  Top 0.254: v76.2,11.05 76.2,11.18 77.22,11.18 C1.1 | L3.1 26.29,59.31 20.19,53.21 16.76,53.21 16.76,52.7 D2.A 15.37,51.44 14.1,51.44 U1.3 14.1,48.26 C5.1 17.02,47.37 17.02,44.45 17.53,43.94 C6.+ | v29.59,10.67 27.43,12.83 v27.43,19.05 | v11.81,19.56 9.14,22.23 v9.14,31.11
  Bottom 0.254: SV1.4 94.11,9.4 92.84,8.13 92.84,4.7 83.82,4.7 83.31,5.21 78.74,5.21 78.11,5.84 J100.P$5 78.11,8.64 78.11,10.16 77.6,10.67 76.58,10.67 v76.2,11.05 75.69,11.18 60.58,11.18 60.07,10.67 v29.59,10.67 | v27.43,19.05 20.07,19.05 19.56,19.56 v11.81,19.56 | v9.14,31.11 4.7,35.56 4.7,42.93 17.02,42.93 C6.+
+5V  (via drill 0.61)
  Top 0.203: D1.A 2.54,41.91 | C4.1 2.54,44.45 | U1.2 13.97,41.91 | D7.A 83.82,72.39 | C7.1 71.12,44.45
  Top 0.254: SV2.2 91.06,26.16 90.17,27.05 90.17,30.86 91.06,31.75 91.06,32.26 SV3.2 | D7.A 84.96,73.03 84.96,73.79 94.74,73.79 v94.74,50.8 94.74,36.83 95.89,35.69 95.89,32 C25.1 94.36,32 94.36,32.89 v94.23,33.02 | v72.9,58.42 72.9,55.88 U3.8 72.01,54.61 71.12,53.72 71.12,45.34 C7.1 70.61,43.56 69.85,42.8 69.85,34.67 68.96,33.78 SV3.20 68.96,32.26 69.85,31.37 69.85,27.05 68.96,26.16 SV2.20 68.2,24.64 67.44,23.88 67.44,19.81 v66.17,18.54 | U2.3 C9.+ 2.41,48.77 2.41,45.34 C4.1 2.16,43.56 2.16,42.55 D1.A 2.79,42.55 4.32,42.55 4.32,42.8 4.57,43.05 6.73,43.05 6.73,34.04 | U1.2 13.34,41.4 11.05,39.12 11.05,38.86 IC2.16 10.54,36.07 9.65,35.18 9.65,34.8 8.89,34.04 6.73,34.04 | 6.73,34.04 5.84,34.04 5.84,22.99 4.83,21.97 L2.1 4.32,21.21 4.32,19.3 R6.1 4.7,17.53 4.7,15.49 C20.1 4.7,13.72 4.7,7.24 C2.1 4.7,5.46 4.7,4.7 SV4.5 4.83,1.65 4.83,0.64 31.88,0.64 35.43,4.19 38.48,4.19 C19.1 39.24,5.97 39.24,6.86 IC1.10 39.62,9.65 39.62,17.27 v39.75,17.4
  Bottom 0.254: J1.2 v94.74,50.8 95,51.31 96.77,51.31 96.77,54.23 92.2,58.8 73.28,58.8 v72.9,58.42 | v94.23,33.02 SV3.2 | SV5.5 20.19,2.03 18.8,0.64 6.6,0.64 5.21,2.03 SV4.5 | v66.17,18.54 47.62,18.54 46.48,17.4 v39.75,17.4
AGND  (via drill 0.61)
  Top 0.203: 26.67,55.88 C12.2 25.78,56.77
  Top 0.254: C8.2 4.32,25.65 4.32,27.56 L4.2 4.83,28.32 5.33,28.83 5.33,35.69 v5.71,36.07 | IC1.31 39.12,24.89 39.12,25.65 38.99,25.78 C3.2 37.59,27.56 37.59,41.91 v37.47,42.04 | v33.4,45.34 33.4,48.77 27.18,54.99 C12.2
  Bottom 0.254: v37.47,42.04 36.7,42.04 v33.4,45.34 32.89,45.09 25.53,45.09 22.35,41.91 11.56,41.91 v5.71,36.07
AREF
  Top 0.203: L3.2 29.21,59.69 | C12.1 29.21,55.88
  Top 0.254: L3.2 29.08,59.31 29.08,56.77 C12.1
BLAH1  (via drill 0.61)
  Top 0.203: R10.1 76.2,45.72
  Top 0.254: v76.83,43.81 76.83,44.83 R10.1
  Bottom 0.203: C103.1 78.74,43.18 | R103.1 78.74,48.26 | R104.2 78.74,53.34
  Bottom 0.254: v76.83,43.81 77.85,43.81 C103.1 78.61,44.07 78.61,47.37 R103.1 78.61,49.15 78.61,52.45 R104.2
CLK1  (via drill 0.61)
  Top 0.254: R7.1 80.39,5.33 80.39,6.1 R8.2 80.39,7.87 79.38,8.89 v79.38,9.65 | v85.6,14.61 84.96,14.61 84.96,12.45 v83.95,11.43
  Bottom 0.254: J100.P$4 79.38,8.64 v79.38,9.65 79.63,10.16 80.26,10.79 83.31,10.79 v83.95,11.43 | v85.6,14.61 92.46,14.61 93.85,13.21 SV1.5
CLK2  (via drill 0.61)
  Top 0.254: v82.93,1.65 82.93,5.84 83.19,6.1 R8.1 83.44,7.87 83.44,10.29 82.93,10.79 82.93,13.46 83.44,13.97 83.44,21.46 v84.07,22.1 | v69.85,21.59 69.85,26.29 70.74,27.18 SV2.17
  Bottom 0.254: v82.93,1.65 82.42,2.16 72.52,2.16 70.99,3.68 52.58,3.68 52.07,4.19 37.97,4.19 34.92,7.24 IC1.8 | J1.7 89.53,42.8 90.55,41.78 91.95,41.78 97.28,36.45 97.28,24.13 92.71,24.13 90.68,22.1 v84.07,22.1 70.36,22.1 v69.85,21.59
CS1  (via drill 0.61)
  Top 0.254: R3.2 74.55,6.1 74.55,5.33 R2.1 74.04,5.21 v73.15,5.21
  Bottom 0.254: v73.15,5.21 73.28,5.33 75.44,5.33 75.88,5.78 | 75.88,5.78 75.95,5.84 J100.P$7 | SV1.1 93.73,2.92 92.96,3.68 77.98,3.68 75.88,5.78
CS2  (via drill 0.61)
  Top 0.254: v70.48,2.67 70.48,6.1 R3.1 | v35.31,28.57 33.66,30.23 v33.66,32.77 | v26.29,20.07 26.42,19.94 26.42,9.65 IC1.5
  Bottom 0.254: v70.48,2.67 52.83,2.67 51.82,3.68 33.15,3.68 30.48,6.35 28.19,6.35 27.3,7.24 IC1.5 | v35.31,28.57 50.04,28.57 50.29,28.83 64.26,28.83 64.64,29.21 69.85,29.21 69.85,27.43 70.61,26.67 77.09,26.67 77.98,27.56 SV2.11 | v33.66,32.77 24.13,32.77 22.1,30.73 22.1,26.42 17.14,26.42 15.37,24.64 15.37,20.07 v26.29,20.07
GND  (via drill 0.61)
  Top 0.203: U1.1 8.89,41.91 | C4.2 5.08,44.45 | R9.1 2.54,38.1 | FB1.2 15.24,67.31 | R11.1 22.86,49.53 | C5.2 19.05,48.26 | Q1.E 83.82,62.23 | R19.1 81.28,63.5 | C7.2 68.58,44.45
  Top 0.254: J1.4 J1.6 J1.8 J1.10 SV3.1 | R19.1 82.17,62.61 83.31,62.61 Q1.E 83.57,62.1 83.57,54.86 | 83.57,54.86 v83.57,50.55 | C11.2 39.88,3.43 41.4,4.95 C19.2 41.91,5.97 IC1.11 | R7.2 79.12,1.78 78.36,1.78 R4.2 76.58,1.78 75.82,1.78 R2.2 74.04,1.65 59.31,1.65 C10.2 57.91,2.79 v56.01,4.7 | 81.41,9.78 81.41,9.02 82.42,8 82.42,4.06 80.9,2.54 R7.2 | 81.41,9.78 81.41,11.18 C1.2 | 81.41,9.78 v80.9,9.78 | R7.2 80.9,1.02 80.9,0.64 95.89,0.64 97.28,2.03 97.28,5.97 96.39,6.86 SV1.3 96.39,8.38 97.28,9.27 97.28,13.59 96.39,14.48 SV1.6 96.39,16 97.28,16.89 97.28,26.54 96.14,27.69 C25.2 94.36,28.32 92.2,28.32 SV2.1 91.82,28.7 91.82,29.34 93.22,30.73 93.22,35.05 v93.73,35.56 | SV4.6 1.78,4.7 1.78,5.46 C2.2 1.78,7.24 1.78,13.72 C20.2 2.41,15.49 3.17,16.26 3.17,27.05 2.67,27.56 L4.1 2.16,28.32 2.16,37.21 R9.1 3.17,38.99 3.68,39.5 v3.68,41.53 | SV2.19 68.2,28.7 67.31,29.59 67.31,33.91 68.2,34.8 SV3.19 68.58,43.56 C7.2 67.69,45.34 66.42,46.61 66.42,46.99 U3.4 | C6.- 20.07,43.94 20.07,47.24 19.94,47.37 C5.2 19.94,49.15 21.97,49.15 R11.1 23.75,48.64 23.75,43.05 27.18,39.62 27.18,27.81 26.92,27.56 C23.2 | C17.- 6.6,75.56 4.95,73.91 4.95,59.69 | U1.1 9.14,41.4 9.14,36.45 C24.2 | IC2.15 13.59,38.86 14.61,39.88 14.61,43.18 14.35,43.43 9.53,43.43 9.53,42.93 U1.1 | U1.1 8.76,42.93 8.76,43.56 5.97,43.56 C4.2 5.33,45.34 5.33,48.77 C9.- 5.33,50.29 5.33,59.69 | v80.01,54.86 83.57,54.86
  Top 0.61: C13.2 18.41,78.11 18.41,73.03 14.61,69.22 14.61,67.31
  Top 1.016: FB1.2 14.61,67.31 14.61,59.69 5.33,59.69 4.95,59.69 U2.2
  Bottom 0.203: R103.2 81.28,48.26 | C103.2 81.28,43.18
  Bottom 0.254: 82.74,49.72 82.17,49.15 R103.2 81.53,47.37 81.53,44.07 C103.2 | v83.57,50.55 82.74,49.72 | J1.4 90.81,48.64 89.79,49.66 82.8,49.66 82.74,49.72 | v80.9,9.78 80.64,9.78 80.64,8.64 J100.P$3 | v56.01,4.7 45.09,4.7 42.55,7.24 IC1.11 | SV3.1 v93.73,35.56 | SV5.6 17.65,4.32 16.76,5.21 3.56,5.21 2.67,4.32 SV4.6 | 43.31,49.66 43.31,49.15 C100.2 42.67,47.37 41.66,46.35 25.02,46.35 22.1,43.43 21.08,43.43 C6.- 19.56,43.43 13.72,49.28 5.84,49.28 C9.- 4.7,48.9 3.68,48.9 v3.68,41.53 | 43.31,49.66 43.31,52.45 R100.2 44.07,54.23 44.58,54.74 48.39,54.74 48.9,54.23 R101.2 50.42,52.45 50.93,51.94 57.28,51.94 | 43.31,49.66 48.51,49.66 49.02,49.15 C101.2 | 57.28,51.94 57.28,49.15 C102.2 58.04,47.62 U3.4 66.29,48.26 71.88,53.85 73.91,53.85 74.8,54.74 79.88,54.74 v80.01,54.86 | 57.28,51.94 57.28,52.45 R102.2
GND1  (via drill 1.6)
  Top 0.203: FB1.1 17.78,67.31 | C14.2 22.86,66.04 | C16.2 78.74,68.58
  Top 0.254: 79.63,64.9 82.04,64.9 82.68,64.26 82.68,63.5 84.84,63.5 85.09,63.25 85.09,58.93 U4.3 | 79.63,64.9 79.63,67.06 C16.2 78.74,68.83 C18.- | 79.63,64.9 77.47,62.74 71.63,62.74 71.63,63.63 59.31,75.95 J3.2
  Top 1.016: FB1.1 18.41,67.31 18.41,66.27 C14.2
  Top 1.778: C14.2 27.94,66.27 | 27.94,66.27 C15.- | J2.2 30.48,74.93 30.48,66.27 27.94,66.27
  Top 2.54: J3.2 54.61,74.93 54.61,74.65 D4.1 49.53,74.65 | 49.53,74.65 D4.3 | v49.53,77.47 49.53,74.65
  Bottom 2.54: J2.2 30.48,74.93 30.48,71.12 49.53,71.12 v49.53,77.47
IBAT  (via drill 0.61)
  Top 0.203: R13.2 59.69,55.88
  Top 0.254: U3.1 64.01,55.5 60.58,55.5 R13.2 58.8,55.24 55.75,52.2 v55.75,45.34 | v59.56,21.08 61.21,19.43 v61.21,14.1 | v72.01,13.59 80.9,22.48 80.9,24.64 SV2.10 | v44.83,44.32 41.78,41.27 v41.78,32.51 | v24.89,31.75 24.64,31.5 24.64,28.32 24.51,28.19 24.51,24.77 IC1.37
  Bottom 0.254: v59.56,21.08 59.05,20.57 45.34,20.57 44.83,21.08 26.16,21.08 24.77,22.48 IC1.37 | v61.21,14.1 71.5,14.1 v72.01,13.59 | v55.75,45.34 54.74,44.32 v44.83,44.32 | v41.78,32.51 41.02,31.75 v24.89,31.75
IIN-  (via drill 0.61, 1.6)
  Top 0.203: R16.2 88.9,55.88 | R17.1 72.39,71.12 72.39,64.77 73.38,64.77 | C16.1 76.2,68.58
  Top 0.254: R16.2 88.01,56.52 88.01,56.64 85.34,56.64 U4.1 84.58,56.64 v84.58,54.36 | 73.66,67.94 C16.1 | 73.66,71.12 74.68,71.88 75.82,73.03 C18.+ 76.45,74.42 76.45,74.93 94.36,74.93 95.25,74.04 95.25,54.23 v95.76,53.72
  Top 1.778: R26.1 R25.1 R17.1
  Top 2.54: 73.38,64.77 73.66,64.77 73.66,67.94 73.66,71.12 | M1.2 73.38,64.77 | 73.38,64.77 v76.2,64.77 | v74.93,78.11 73.66,78.11
  Bottom 0.203: R104.1 81.28,53.34
  Bottom 0.254: R104.1 82.17,54.23 82.3,54.36 v84.58,54.36 85.09,54.1 85.47,53.72 v95.76,53.72
  Bottom 1.778: 73.66,71.12 72.39,71.12 72.39,78.11 73.66,78.11
  Bottom 2.54: v76.2,64.77 73.66,64.77 73.66,71.12 | 73.66,78.11 v74.93,78.11
IOUT+  (via drill 0.61)
  Top 0.254: v43.31,60.2 43.31,62.1 D3.4
  Top 1.778: 43.18,71.12 R23.2 43.18,72.39 | R24.2 45.72,72.39 43.18,72.39 | R22.2 40.64,72.39 43.18,72.39
  Top 2.54: D3.4 43.14,71.12 43.18,71.12
  Bottom 0.254: v43.31,60.2 43.31,59.31 R105.1
IPANEL  (via drill 0.61)
  Top 0.203: R14.2 76.2,53.34
  Top 0.254: U3.7 74.42,52.96 75.31,52.96 R14.2 77.09,54.1 v79.63,51.56 | v19.81,31.75 19.81,28.96 19.3,28.45 19.3,24.89 IC1.39 | v59.56,34.04 62.87,37.34 v62.87,41.02 | v93.34,29.34 93.85,29.34 94.61,30.1 96.65,30.1 v96.65,44.7
  Bottom 0.254: v19.81,31.75 22.1,34.04 v59.56,34.04 | v62.87,41.02 63.37,41.53 66.55,41.53 70.1,45.09 74.93,45.09 75.44,45.59 75.44,52.07 74.04,52.07 U3.7 | v93.34,29.34 90.17,29.34 90.17,24.89 88.52,23.24 86.61,23.24 86.61,24.64 SV2.6 | v96.65,44.7 91.69,49.66 90.93,49.66 90.04,50.55 90.04,51.94 80.01,51.94 v79.63,51.56
MISO  (via drill 0.61)
  Top 0.254: v82.42,17.91 v82.42,9.78 | v35.31,36.07 32.64,33.4 32.64,25.91 32.89,25.65 32.89,10.54 32,9.65 IC1.7 | v74.93,41.15 74.93,29.59 74.04,28.7 SV2.15 | v92.2,18.92 93.09,19.81 v93.09,27.3
  Bottom 0.254: v82.42,9.78 81.66,9.02 81.66,8.64 J100.P$2 | 92.2,17.91 93.73,17.91 SV1.7 | 92.2,17.91 v82.42,17.91 | v35.31,36.07 39.24,40.01 72.39,40.01 73.41,41.02 74.93,41.02 | 74.93,41.02 88.27,41.02 J1.9 | 74.93,41.02 v74.93,41.15 | v92.2,18.92 92.2,17.91 | v93.09,27.3 94.36,28.57 94.36,31.5 84.84,31.5 82.55,29.21 75.31,29.21 74.42,28.32 SV2.15
MOSI1  (via drill 0.61)
  Top 0.254: R4.1 77.09,5.33 v77.09,9.65 77.6,9.4 79.38,11.18 79.38,16.64 77.85,16.64 76.2,14.99 76.2,13.34 74.55,11.68 R5.2
  Bottom 0.254: v77.09,9.65 77.09,8.64 J100.P$6 77.09,5.84 78.23,4.7 83.06,4.7 83.57,4.19 93.22,4.19 93.73,4.7 SV1.2
MOSI2  (via drill 0.61)
  Top 0.254: v69.22,10.16 70.23,10.16 R5.1 70.99,11.68 70.99,20.95 74.93,24.89 74.93,26.29 75.82,27.18 SV2.13 76.58,28.7 76.58,31.24 77.47,32.13 77.47,34.29 81.79,34.29 82.55,33.53 82.55,32.51 82.8,32.26 82.8,31.75 84.33,31.75 85.09,32.51 85.09,36.07 86.36,37.34 86.36,48.01 88.52,50.16 J1.1
  Bottom 0.254: v69.22,10.16 30.73,10.16 29.84,9.27 IC1.6
N$1
  Top 0.254: C13.1 14.73,77.22 14.35,76.83 14.35,76.33 D6.C
  Top 1.016: R27.1 2.54,78.74 9.53,78.74 C17.+ 9.53,75.56 D6.C D5.C
N$2
  Top 0.254: C22.1 18.16,27.56 18.16,28.45 IC2.4
N$3
  Top 1.016: U2.1 R27.2
N$4
  Top 0.254: C22.2 20.7,27.56 20.7,28.45 IC2.5
N$5
  Top 0.203: D1.C 5.08,41.91 | R9.2 5.08,38.1
  Top 0.254: D1.C 5.59,41.27 5.59,38.99 R9.2
N$6
  Top 0.203: D2.C 19.05,52.07 | R11.2 22.86,52.07
  Top 0.254: D2.C 21.97,52.07 R11.2
N$7  (via drill 0.61)
  Top 0.254: C8.1 2.16,23.88 2.16,21.97 L2.2 2.16,21.21 v2.16,20.19 | v41.78,18.54 41.78,22.1 IC1.30
  Bottom 0.254: v41.78,18.54 41.66,18.41 34.29,18.41 33.4,17.53 4.83,17.53 v2.16,20.19
N$8
  Top 0.203: U4.6 82.3,57.02
  Top 0.406: 82.7,56.84 U4.6
  Top 0.61: 81.92,56.52 82.7,56.84
  Top 0.813: R18.2 78.74,60.96 78.74,56.52 81.92,56.52
N$9
  Top 0.203: D7.C 81.28,72.39 | R20.2 81.28,69.85
  Top 0.254: D7.C 80.9,71.75 80.9,70.74 R20.2
N$10  (via drill 0.61)
  Top 0.203: R19.2 81.28,66.04 | R21.1 90.17,64.77 | Q1.B 83.82,64.77
  Top 0.254: R19.2 82.17,66.04 83.31,64.9 Q1.B 84.58,64.9 v85.6,64.9 | v88.27,64.9 89.28,64.9 R21.1
  Bottom 0.254: v85.6,64.9 v88.27,64.9
N$11
  Top 0.254: C21.2 14.86,27.56 15.62,28.32 15.62,28.45 IC2.3
N$12
  Top 0.203: R12.2 59.69,50.8 | R13.1 59.69,53.34
  Top 0.254: R12.2 R13.1 60.58,52.96 64.01,52.96 U3.2
N$13
  Top 0.254: C21.1 11.05,27.56 11.05,28.45 IC2.1
N$14
  Top 0.203: R10.2 76.2,48.26 | R14.1 76.2,50.8
  Top 0.254: R10.2 R14.1 75.31,50.42 74.42,50.42 U3.6
N$15  (via drill 0.61)
  Top 0.254: C11.1 v43.81,2.54 | IC1.12 44.7,6.86 46.23,5.33 46.23,3.17 X2.1
  Bottom 0.254: v43.81,2.54 X2.1
N$16
  Top 0.254: U4.4 82.3,58.8 79.63,58.8 R15.2
N$17
  Top 0.254: C10.1 54.99,2.29 51.94,2.29 X2.2 51.05,3.17 51.05,3.3 47.37,6.99 IC1.13
N$18  (via drill 0.61)
  Top 0.254: v1.91,16.51 1.91,17.53 R6.2 | v36.58,16.13 36.58,9.65 IC1.9 | v79.88,49.91 79.88,46.61 R1.2 | v67.56,41.02 66.42,39.88 v66.42,35.94 | v52.7,35.05 50.67,33.02 v50.67,17.53
  Bottom 0.254: v1.91,16.51 2.29,16.13 v36.58,16.13 37.08,16.38 49.53,16.38 v50.67,17.53 | v79.88,49.91 79.88,41.78 76.33,41.78 74.55,43.56 70.1,43.56 v67.56,41.02 | v66.42,35.94 66.29,36.07 53.72,36.07 v52.7,35.05
N$19  (via drill 0.61)
  Top 0.254: v33.66,26.42 33.66,25.27 34.04,24.89 IC1.33
  Bottom 0.254: v33.66,26.42 67.82,26.42 68.07,26.67 69.47,26.67 70.36,25.78 SV2.18
N$20  (via drill 0.61)
  Top 0.254: v31.88,20.07 31.88,22.1 IC1.34
  Bottom 0.254: v31.88,20.07 61.09,20.07 63.63,22.61 63.63,25.4 66.8,25.4 68.07,24.13 72.01,24.13 72.9,25.02 SV2.16
N$21
  Top 0.203: M1.1 73.66,59.69
  Top 0.813: R15.1 76.2,58.42 76.2,59.69 | 73.66,59.69 76.2,59.69 | R18.1 76.2,60.96 76.2,59.69
N$22  (via drill 0.61)
  Top 0.254: v45.85,21.59 v45.85,19.05
  Bottom 0.254: v45.85,21.59 30.73,21.59 29.84,22.48 IC1.35 | v45.85,19.05 46.35,19.56 64.9,19.56 68.45,23.11 78.23,23.11 80.01,24.89 80.01,26.67 77.85,26.67 76.96,25.78 SV2.14
N$23  (via drill 0.61)
  Top 0.254: v29.59,26.92 29.59,26.8 27.3,24.51 IC1.36 | v62.1,29.84 63.75,31.5 63.75,34.42 64.26,34.92 66.42,34.92 v66.42,24.26
  Bottom 0.254: v29.59,26.92 32.26,29.59 40.77,29.59 41.27,29.08 49.78,29.08 50.55,29.84 v62.1,29.84 | v66.42,24.26 67.06,23.62 76.58,23.62 77.98,25.02 SV2.12
N$24  (via drill 0.61)
  Top 0.203: R16.1 88.9,58.42 | R20.1 83.82,69.85
  Top 0.254: U4.5 v81.28,57.78 | U4.2 v86.36,57.78 88.01,57.78 R16.1 88.01,59.31 88.01,61.98 86.87,63.12 Q1.C 86.61,63.88 86.61,65.91 84.96,65.91 84.96,68.71 84.71,68.96 R20.1
  Bottom 0.254: v81.28,57.78 v86.36,57.78
N$25
  Top 2.54: 40.64,76.2 45.72,76.2
N$26  (via drill 0.61)
  Top 0.254: v68.83,8.64 68.2,9.27 v68.2,16.38
  Bottom 0.254: v68.83,8.64 74.55,8.64 J100.P$8 | v68.2,16.38 71.63,19.81 84.96,19.81 86.74,21.59 92.84,21.59 93.73,22.48 SV1.9
N$27  (via drill 0.61)
  Top 0.254: v19.05,45.47 19.05,42.67 17.27,40.89 17.27,28.96 15.37,27.05 15.37,10.54 16.26,9.65 IC1.1 | v91.31,63.12 92.71,61.72 92.71,35.05 91.95,34.29 90.17,34.29 90.17,31.62 89.41,30.86 89.41,28.57 SV2.3
  Bottom 0.254: v19.05,45.47 40.39,66.8 54.1,66.8 54.23,66.93 69.09,66.93 72.9,63.12 v91.31,63.12
N$28
  Top 0.254: C23.1 23.37,27.56 23.37,28.45 IC2.6
N$29  (via drill 0.61)
  Top 0.254: v91.82,5.71 93.22,5.71 93.22,18.67 94.11,19.56 SV1.8
  Bottom 0.254: v91.82,5.71 83.06,5.71 82.93,5.84 J100.P$1
N$30  (via drill 1.6)
  Top 1.778: 55.88,62.23 v55.88,64.77 | 60.96,62.23 v60.96,64.77
  Top 2.54: 58.42,62.23 55.88,62.23 53.34,62.23 53.34,67.31 52.07,67.31 D4.4 52.07,43.18 L1.P$1 v64.77,43.18 | 58.42,62.23 60.96,62.23 M1.3 | 58.42,62.23 58.99,62.23 | v55.88,64.77 54.61,64.77
N$31
  Top 0.254: C24.1 9.14,33.53 13.34,33.53 13.34,33.66 13.84,34.16 15.37,34.16 15.37,32.51 13.84,30.99 IC2.2
N$32  (via drill 0.61)
  Top 0.254: v16.64,2.67 16.64,5.21 18.29,5.21 20.19,7.11 20.19,9.14 22.73,11.68 22.73,24.64 22.1,25.27 22.1,32.38 25.78,36.07 IC2.10
  Bottom 0.254: v16.64,2.67 15.11,1.14 11.18,1.14 10.29,2.03 SV4.3
N$33
  Top 0.254: IC2.9 29.21,38.48 29.84,38.48 30.1,38.73 36.32,38.73 36.32,28.07 37.08,27.3 37.08,25.53 37.97,24.64 37.97,19.05 35.43,16.51 35.43,4.95 31.62,1.14 7.37,1.14 7.37,1.65 SV4.4
N$34  (via drill 1.6)
  Top 0.254: 35.84,63.5 34.67,63.5
  Top 1.778: C14.1 27.94,63.27 C15.+ v33.02,63.5
  Top 2.54: 35.84,67.31 D3.1 35.84,63.5 D3.3 35.84,62.23 35.56,62.23 35.56,43.18 L1.P$2 v26.67,43.18 | v33.02,63.5 34.67,63.5 35.56,63.5
N$35  (via drill 0.61, 1.6)
  Top 0.254: v48.26,56.9 47.37,57.78 47.37,73.53 46.61,74.3 R24.1
  Top 1.778: R24.1 45.72,74.93 43.18,74.93 | R22.1 40.64,74.93 43.18,74.93 | 43.18,74.93 R23.1 | 43.18,76.2 43.18,74.93 | 43.18,77.47 v45.72,77.47 | D6.A 24.13,78.11 35.56,78.11 35.56,77.47
  Top 2.54: J2.1 35.52,77.47 35.56,77.47 43.18,77.47 43.18,76.2
  Bottom 0.254: v48.26,56.9 48.9,57.53 R106.1
  Bottom 2.54: 35.56,74.93 35.56,77.47 v45.72,77.47
N$36  (via drill 0.61)
  Top 0.254: v34.54,17.14 33.4,16 33.4,9.65 32.89,9.14 32.89,6.1 31.5,4.7 SV5.1
  Bottom 0.254: v34.54,17.14 34.42,17.02 4.45,17.02 3.94,17.53 1.02,17.53 1.02,20.7 1.52,21.21 11.94,21.21 11.94,32.38 15.62,36.07 IC2.14
N$37  (via drill 0.61)
  Top 0.254: v30.61,37.72 30.61,6.35 28.96,4.7 SV5.2
  Bottom 0.254: v30.61,37.72 28.96,39.37 19.94,39.37 19.05,38.48 IC2.13
N$38
  Top 0.254: IC2.7 25.65,28.57 25.02,27.94 25.02,25.02 25.27,24.77 25.27,4.32 SV5.3
N$39  (via drill 0.61)
  Top 0.254: v41.78,30.1 43.31,28.57 43.31,4.57 44.83,3.05 v44.83,1.4
  Bottom 0.254: v41.78,30.1 29.21,30.1 IC2.8 | v44.83,1.4 44.58,1.14 25.15,1.14 24.26,2.03 SV5.4
N$40  (via drill 1.4)
  other vias: 2.54,64.77
N$62  (via drill 0.61)
  Top 0.254: IC1.2 v19.05,18.54
  Bottom 0.254: v19.05,18.54 19.56,18.03 33.15,18.03 34.67,19.56 43.81,19.56 45.34,18.03 46.35,18.03 47.37,19.05 65.15,19.05 68.71,22.61 80.26,22.61 82.55,24.89 82.55,26.67 84.71,26.67 85.6,27.56 SV2.5
N$65
  Top 2.54: 40.64,71.12 45.72,71.12 45.72,67.31 40.64,67.31 40.64,71.12 | 40.64,71.12 44.45,71.12 44.45,68.58 41.91,68.58 41.91,69.85
N$66
  Top 2.54: 64.77,63.5 60.96,63.5 60.96,60.96 63.5,60.96
N$67  (1 unrouted)
N$68  (via drill 0.61)
  Top 0.254: v80.52,15.11 81.41,16 81.41,23.75 82.55,24.89 82.55,26.29 81.66,27.18 SV2.9
  Bottom 0.254: v80.52,15.11 80.01,14.61 70.87,14.61 70.36,15.11 54.48,15.11 53.47,14.1 47.88,14.1 47.75,14.22 29.46,14.22 24.64,9.4 IC1.4
N$69  (via drill 0.61)
  Top 0.254: v53.21,32.38 53.21,10.79 54.36,9.65 IC1.16 | v39.75,33.02 v39.75,60.2 | v85.85,55.37 85.85,37.97 84.2,36.32 SV3.7
  Bottom 0.254: v53.21,32.38 52.07,33.53 40.26,33.53 v39.75,33.02 | v39.75,60.2 42.16,62.61 66.67,62.61 71.88,57.4 80.14,57.4 82.17,55.37 v85.85,55.37
N$70  (via drill 0.61)
  Top 0.254: v49.91,61.59 50.42,61.09 50.42,42.42 56.01,36.83 56.01,10.54 56.9,9.65 IC1.17 | v76.33,56.39 80.9,51.82 80.9,46.86 80.77,46.74 80.77,36.2 SV3.9
  Bottom 0.254: v49.91,61.59 50.42,61.09 67.44,61.09 72.14,56.39 v76.33,56.39
N$71  (via drill 0.61)
  Top 0.254: v62.36,13.08 62.36,22.1 IC1.22 | v83.95,12.95 84.45,13.46 84.45,16.26 87.63,19.43 v87.63,24.26 | v88.39,30.48 88.52,30.61 88.52,32.26 SV3.4
  Bottom 0.254: v62.36,13.08 63.37,12.06 83.06,12.06 v83.95,12.95 | v87.63,24.26 87.63,30.48 v88.39,30.48
N$72  (via drill 0.61)
  Top 0.254: v60.71,27.43 60.71,25.65 59.94,24.89 IC1.23 | v63.37,27.81 63.75,28.19 v63.75,29.84
  Bottom 0.254: v60.71,27.43 61.09,27.81 v63.37,27.81 | v63.75,29.84 64.26,30.35 82.93,30.35 85.22,32.64 85.6,32.64 SV3.6
N$73  (via drill 0.61)
  Top 0.254: v57.4,38.99 57.4,24.89 IC1.24 | v81.79,38.99 82.55,38.23 82.55,34.67 83.44,33.78 SV3.8
  Bottom 0.254: v57.4,38.99 57.91,39.5 72.9,39.5 73.41,38.99 v81.79,38.99
N$74  (via drill 0.61)
  Top 0.254: v54.23,13.34 54.23,21.97 54.36,22.1 IC1.25 | v47.37,13.21 50.93,9.65 v50.93,6.35 | v86.61,19.94 85.09,21.46 85.09,28.7 81.66,32.13 81.66,32.26 SV3.10
  Bottom 0.254: v54.23,13.34 54.1,13.21 v47.37,13.21 | v50.93,6.35 51.56,5.71 71.12,5.71 72.64,4.19 76.2,4.19 77.72,2.67 92.58,2.67 93.98,1.27 96.52,1.27 97.28,2.03 97.28,19.05 93.6,19.05 92.2,20.45 87.12,20.45 v86.61,19.94
N$75  (via drill 0.61)
  Top 0.254: v52.2,17.53 52.2,22.1 IC1.26 | v73.66,21.08 77.47,24.89 77.47,31.37 78.36,32.26 SV3.12
  Bottom 0.254: v52.2,17.53 66.67,17.53 67.18,18.03 67.18,20.32 72.9,20.32 v73.66,21.08
N$76  (via drill 0.61)
  Top 0.254: v78.36,15.62 76.71,13.97 76.71,13.08 75.18,11.56 75.18,9.4 71.12,9.4 69.47,7.75 69.47,2.67 66.67,2.67 66.17,3.17 66.17,5.71 54.86,5.71 53.47,7.11 53.47,9.14 49.66,12.95 49.66,22.1 IC1.27 | v74.17,17.4 80.01,23.24 v80.01,31.88
  Bottom 0.254: v78.36,15.62 77.98,16 75.56,16 v74.17,17.4 | v80.01,31.88 79.88,31.75 77.85,31.75 76.96,32.64 SV3.14
N$77  (via drill 0.61)
  Top 0.254: v47.75,30.35 47.75,25.4 47.24,24.89 IC1.28
  Bottom 0.254: v47.75,30.35 48.77,31.37 61.72,31.37 63.25,32.89 66.93,32.89 68.07,31.75 72.01,31.75 72.9,32.64 SV3.16
N$78  (via drill 0.61)
  Top 0.254: v44.58,36.07 44.58,24.89 IC1.29
  Bottom 0.254: v44.58,36.07 45.47,36.96 71.5,36.96 72.39,36.07 72.39,33.78 71.5,33.78 SV3.18
N$79  (via drill 0.61)
  Top 0.254: v58.55,41.02 58.55,10.54 59.44,9.65 IC1.18 | v74.42,46.1 75.18,46.86 77.98,46.86 77.98,35.94 SV3.11
  Bottom 0.254: v58.55,41.02 58.55,43.81 60.71,45.97 74.3,45.97 v74.42,46.1
N$80  (via drill 0.61)
  Top 0.254: v65.41,37.97 61.09,33.66 61.09,28.57 63.37,26.29 63.37,10.79 64.52,9.65 IC1.20
  Bottom 0.254: v65.41,37.97 65.91,37.47 71.88,37.47 73.15,36.2 SV3.15
N$81  (via drill 0.61)
  Top 0.254: IC1.21 v64.77,33.91
  Bottom 0.254: v64.77,33.91 65.15,34.29 69.47,34.29 70.36,35.18 SV3.17
PWM  (via drill 0.61)
  Top 0.254: v94.87,34.54 94.87,35.94 93.73,37.08 v93.73,59.31 93.73,63.75 93.6,63.88 R21.2 | v59.56,11.68 59.56,11.56 61.72,9.4 IC1.19 | v42.29,12.19 40.77,13.72 40.77,60.71 39.12,62.36 v39.12,63.5 | v70.1,63.63 71.12,62.61 v71.12,61.59
  Bottom 0.254: v94.87,34.54 94.61,34.29 77.85,34.29 76.96,35.18 SV3.13 | v59.56,11.68 59.05,12.19 v42.29,12.19 | v39.12,63.5 41.91,66.29 54.36,66.29 54.48,66.42 67.31,66.42 v70.1,63.63 | v71.12,61.59 73.28,59.44 89.66,59.44 89.79,59.31 v93.73,59.31
RESET  (via drill 0.61)
  Top 0.254: R1.1 v84.84,45.72
  Bottom 0.254: v84.84,45.72 J1.5
RXD1  (via drill 0.61)
  Top 0.254: v12.95,22.99 12.83,22.86 12.83,9.53 | 12.83,9.53 12.83,4.32 SV4.2 | v44.96,13.21 48.9,9.27 IC1.14 | v17.65,6.35 15.62,6.35 15.62,6.73 12.83,9.53 | v90.3,60.33 90.3,37.34 89.28,36.32 SV3.3 | v21.59,44.45 21.59,38.48 IC2.12
  Bottom 0.254: v12.95,22.99 16.89,26.92 17.02,26.92 17.02,32.38 20.7,36.07 IC2.12 | v44.96,13.21 29.34,13.21 25.27,9.14 25.27,6.35 v17.65,6.35 | v90.3,60.33 88.01,62.61 67.44,62.61 66.93,63.12 40.26,63.12 v21.59,44.45
TXD1  (via drill 0.61)
  Top 0.254: 49.02,30.35 49.02,25.27 48.39,24.64 v48.39,15.11 48.39,13.08 51.82,9.65 IC1.15 | 49.02,30.35 v49.02,35.05 | SV4.1 v14.61,6.22 | 49.02,30.35 v49.28,30.35
  Bottom 0.254: v49.02,35.05 25.53,35.05 24.13,36.45 IC2.11 | v14.61,6.22 14.61,15.11 v48.39,15.11 | v49.28,30.35 49.78,30.86 74.93,30.86 74.93,36.07 75.69,36.83 84.33,36.83 84.58,36.58 84.96,36.58 85.6,35.94 SV3.5
VBAT  (via drill 0.61)
  Top 0.203: R12.1 59.69,48.26
  Top 0.254: v46.1,55.75 45.09,54.74 v45.09,53.72 45.34,53.21 45.85,52.7 45.85,25.65 v45.59,25.4 | v57.78,46.35 58.8,47.37 R12.1 60.58,47.37 60.58,46.48 64.52,46.48 66.42,44.58 66.42,41.02 v63.88,38.48
  Bottom 0.254: 50.93,46.86 50.93,49.4 50.67,49.66 50.42,49.66 47.62,52.45 R101.1 46.1,53.72 v45.09,53.72 | 50.93,46.86 48.01,46.86 47.5,47.37 C101.1 | v46.1,55.75 46.1,57.53 R106.2 | v57.78,46.35 57.28,46.86 50.93,46.86 | v45.59,25.4 23.11,25.4 22.23,24.51 IC1.38 | v63.88,38.48 64.39,38.99 65.91,38.99 66.93,37.97 83.95,37.97 84.84,37.08 95.89,37.08 95.89,28.57 93.6,26.29 93.22,26.29 93.22,25.4 90.55,22.73 86.36,22.73 84.33,24.77 SV2.8
VDD
  Top 0.254: C3.1 36.07,25.78 36.58,25.27 36.58,24.89 IC1.32
VIN  (via drill 0.61, 1.6)
  Top 0.203: 69.7,72.39 69.85,72.39
  Top 0.254: v48.39,67.82 v48.39,60.07
  Top 1.016: 68.58,72.39 69.85,72.39 69.85,71.12 69.85,78.11
  Top 1.27: 68.58,71.75 69.85,71.75 69.85,71.12
  Top 1.778: R25.2 69.85,74.93 | 68.58,74.93 R25.2 | 69.85,78.11 R26.2 | R25.2 69.7,72.39 R17.2 69.85,71.12
  Top 2.54: J3.1 68.58,74.93 | v67.31,72.39 v67.31,77.47 | R26.2 68.58,78.11 68.58,72.39
  Bottom 0.254: v48.39,60.07 55.75,60.07 56.52,59.31 R107.1 | 48.39,68.58 v48.39,67.82
  Bottom 1.778: 68.58,74.93 69.85,74.93 | 69.85,74.93 69.85,78.11 | 69.85,74.93 69.85,71.12 | D5.A 24.13,68.58 48.39,68.58 63.5,68.58 63.5,74.93
  Bottom 2.54: J3.1 63.5,74.93 67.31,74.93 | 67.31,74.93 68.58,74.93 | 67.31,74.93 v67.31,72.39 | 67.31,74.93 v67.31,77.47
VOP+  (via drill 0.61)
  Top 0.254: v67.31,56.39 67.31,51.69 66.42,50.8 U3.3
  Bottom 0.254: C100.1 40.51,49.15 40.51,52.45 R100.1 40.51,54.23 40.51,57.53 R105.2 40.89,59.31 42.8,61.21 48.77,61.21 49.4,60.58 63.12,60.58 v67.31,56.39
VPANEL  (via drill 0.61)
  Top 0.254: v54.48,55.12 v54.48,50.93 54.23,50.42 v54.23,45.85 | v31.62,27.43 32.13,27.94 v32.13,36.07 | v87.63,38.1 87.63,32.51 87.38,32.26 87.38,29.97 87.63,29.72 87.63,27.05 88.52,26.16 SV2.4 | v73.91,40.01 73.41,40.51 73.41,46.99 U3.5
  Bottom 0.254: R102.1 54.48,54.23 v54.48,55.12 54.48,57.53 R107.2 | v54.48,50.93 54.48,49.15 C102.1 | v31.62,27.43 30.1,25.91 18.54,25.91 17.14,24.51 IC1.40 | v32.13,36.07 37.08,41.02 54.99,41.02 58.36,44.39 | 58.36,44.39 60.45,46.48 70.74,46.48 71.63,47.37 U3.5 | v87.63,38.1 85.72,40.01 v73.91,40.01 | v54.23,45.85 54.74,46.35 56.26,46.35 58.17,44.45 58.29,44.45 58.36,44.39

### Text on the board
tPlace: FreeCharge- | Controller.org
